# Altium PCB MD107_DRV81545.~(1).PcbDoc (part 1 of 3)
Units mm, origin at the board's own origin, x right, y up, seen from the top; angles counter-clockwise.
Board outline 152.45 x 74.46 mm, 4 copper layers (Top Layer, Mid-Layer 1, Mid-Layer 2, Bottom Layer), stack 2.355 mm thick; 219 components, 121 nets, 695 pads, 224 vias.
Unrouted connection lines stored in the file: 85.
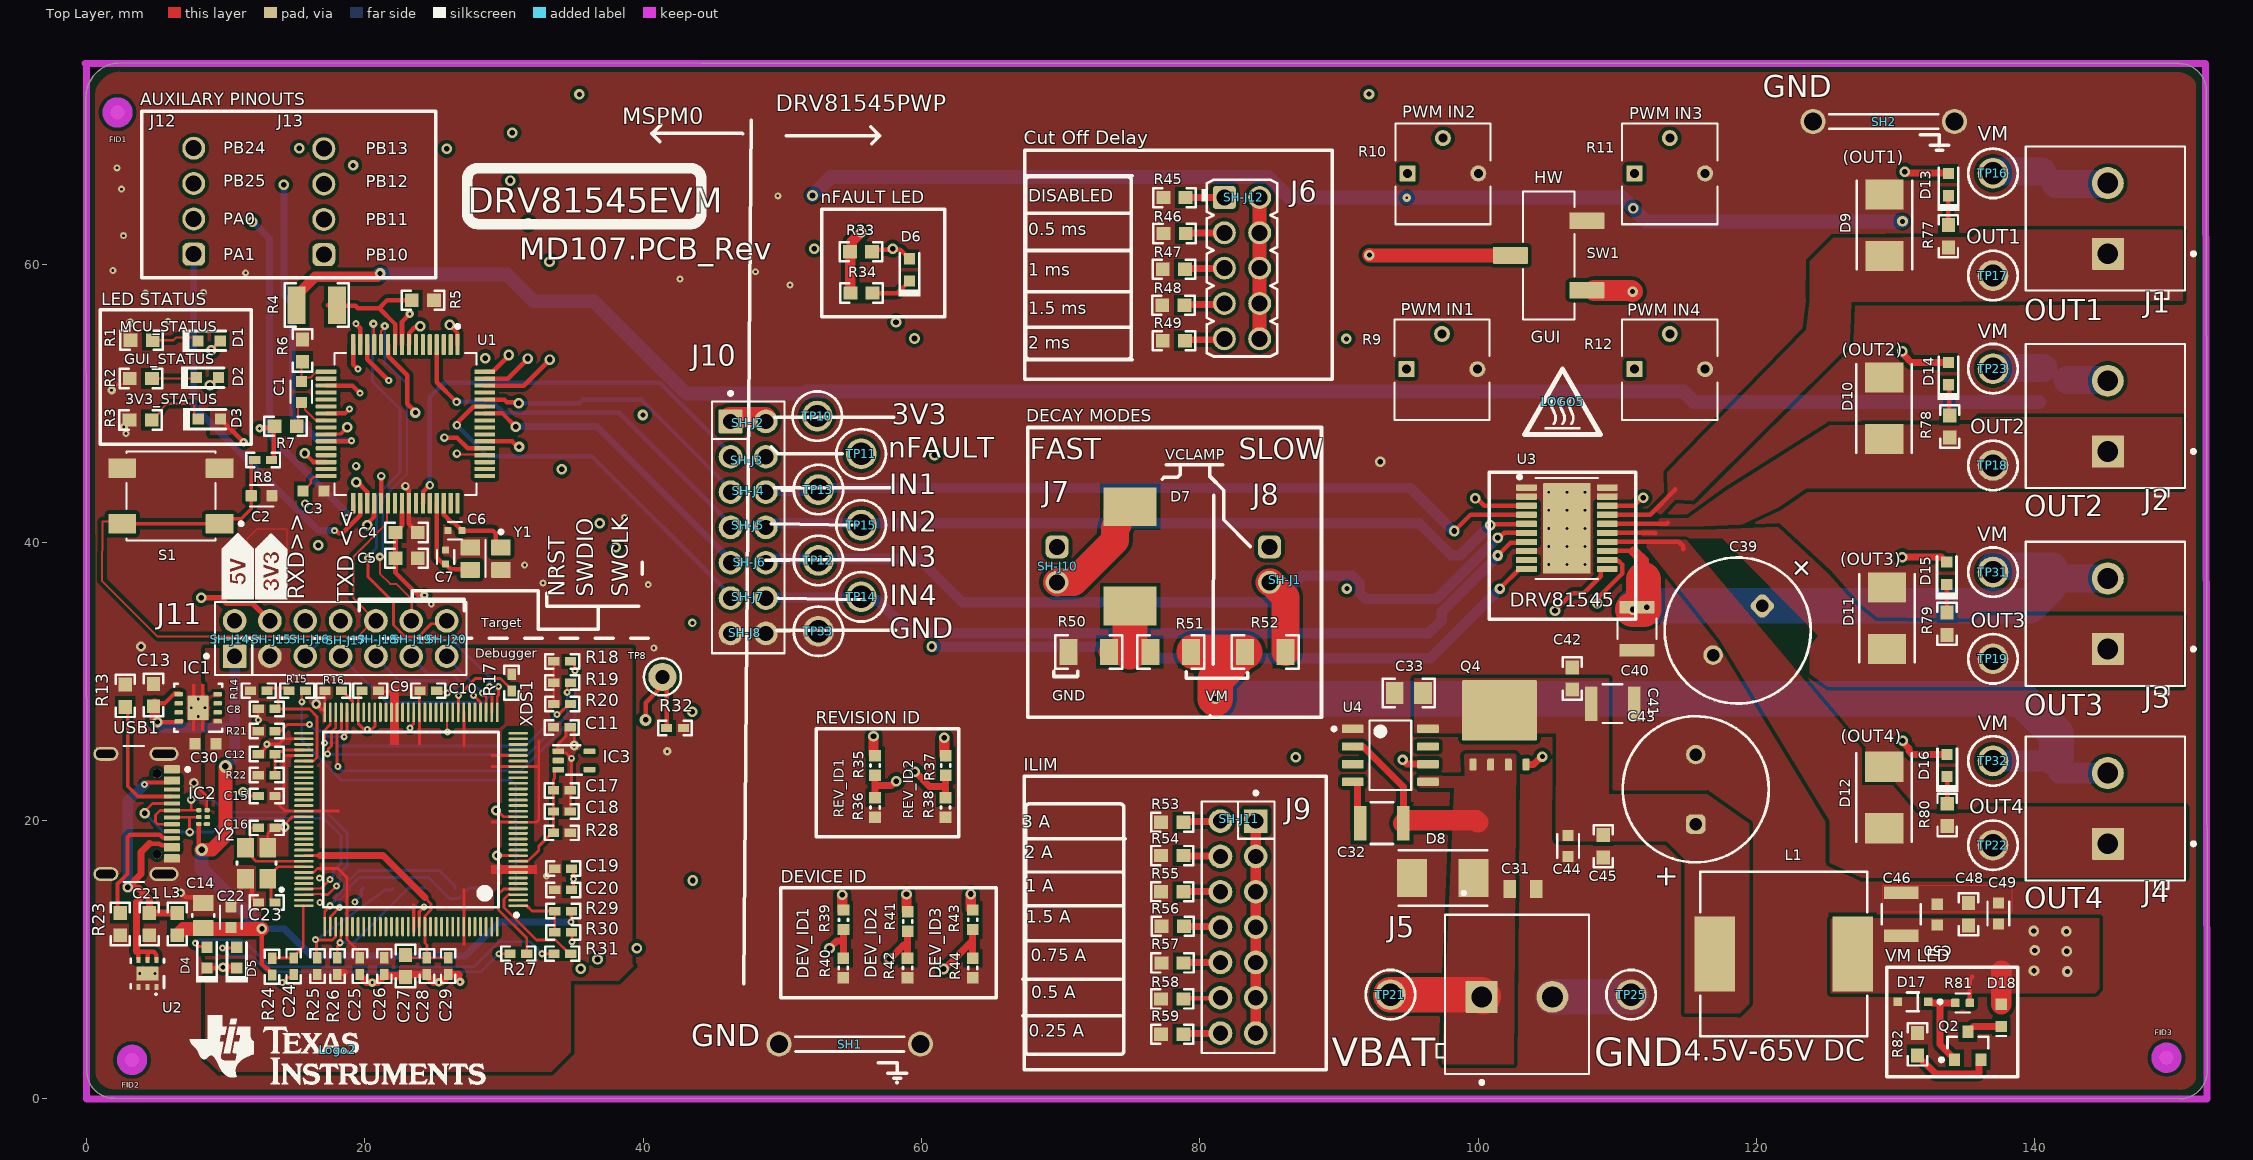
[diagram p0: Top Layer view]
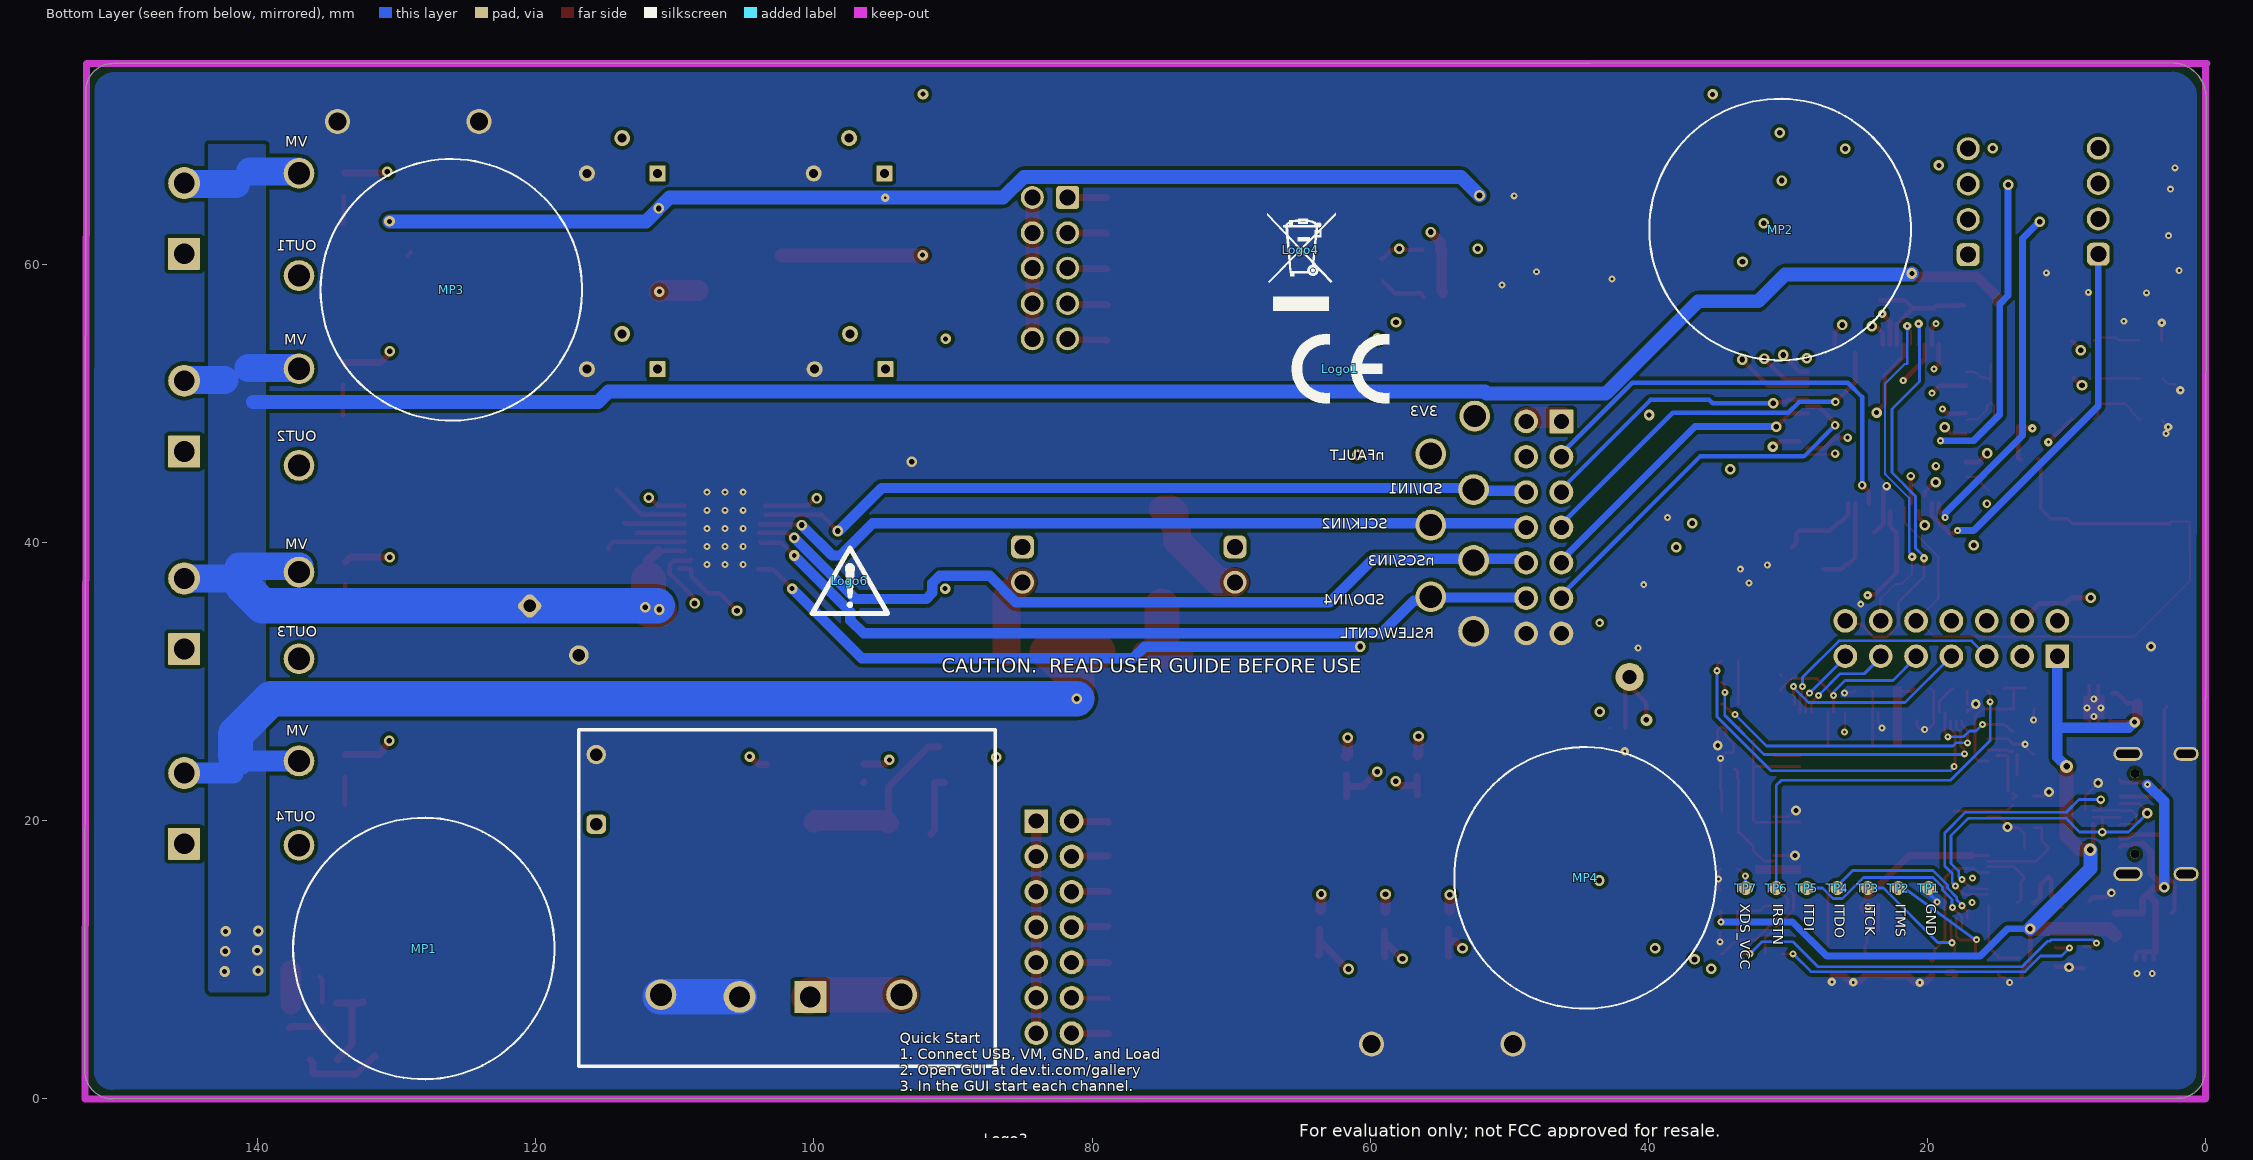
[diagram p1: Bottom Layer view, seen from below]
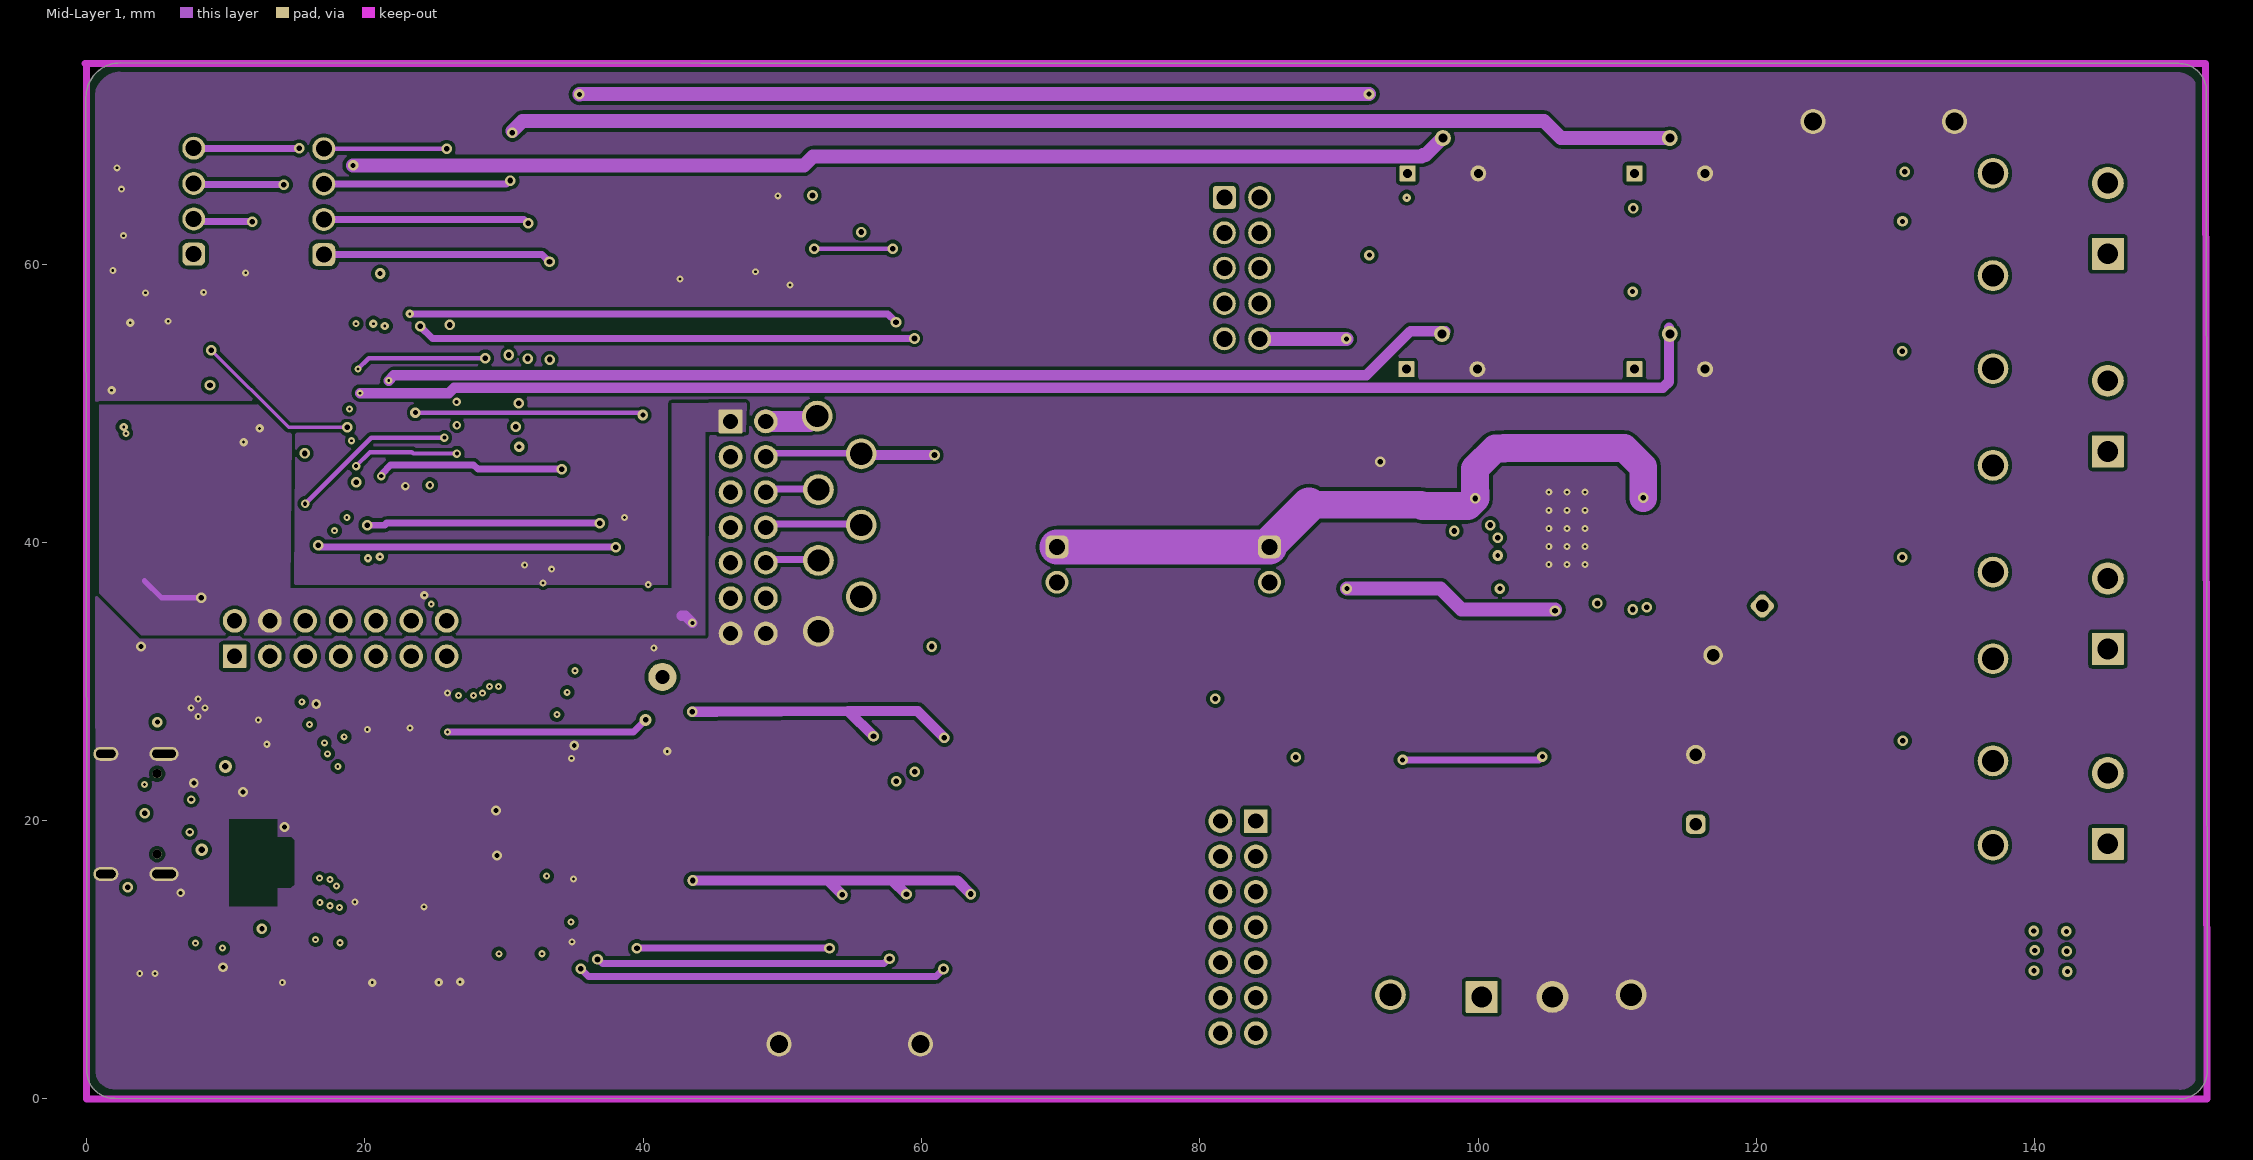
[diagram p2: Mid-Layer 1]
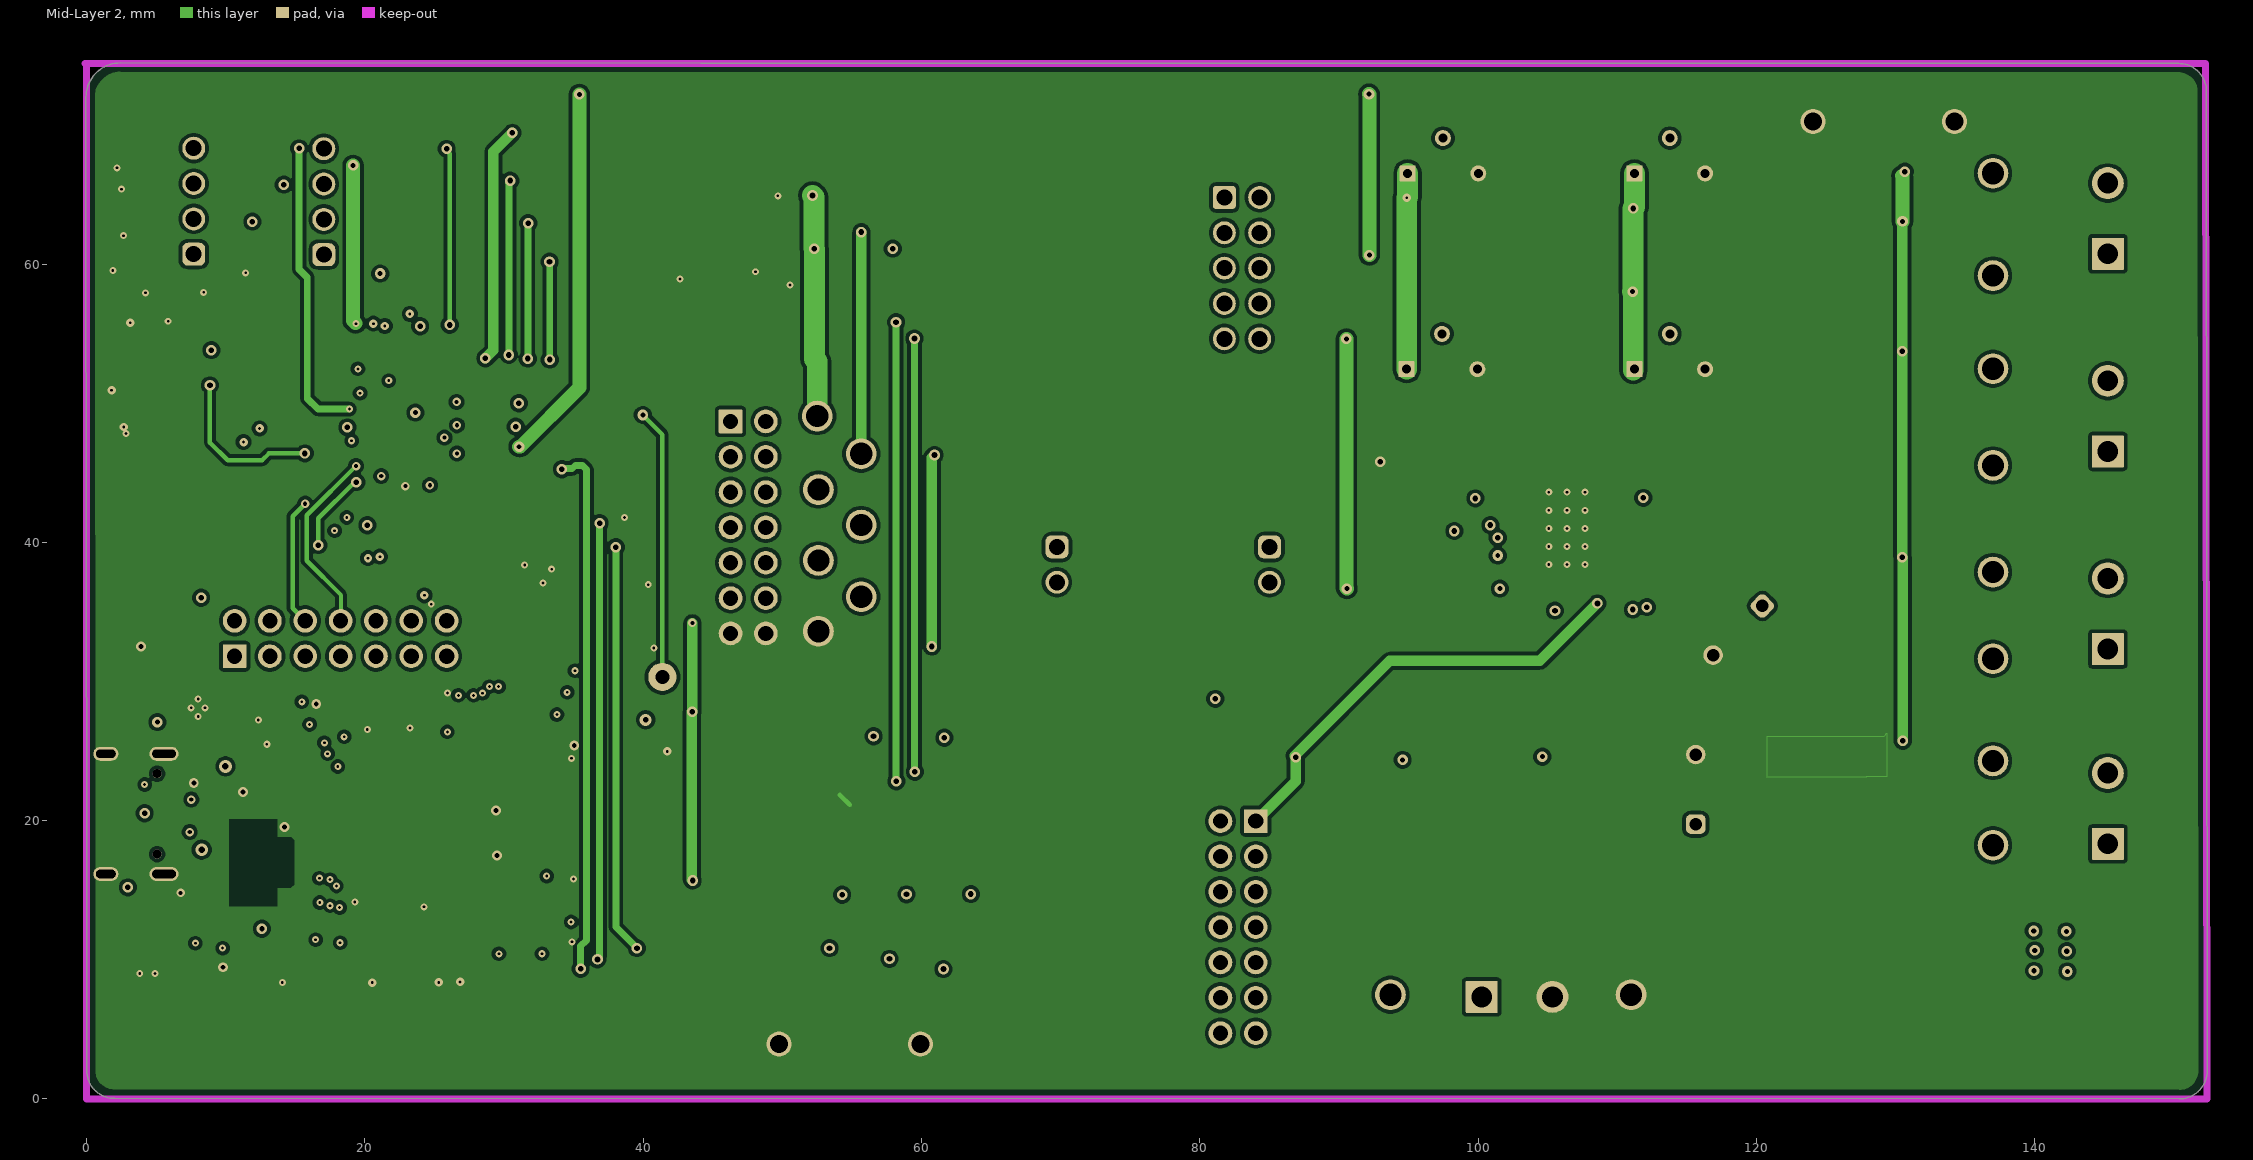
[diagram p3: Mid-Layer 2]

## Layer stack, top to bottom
Top Solder: solder mask 0.0102, Solder Resist, Dk 3.5
Top Layer: signal copper 0.07
Dielectric1: core 1.5037, FR-4 High Tg, Dk 4.8
Mid-Layer 1: signal copper 0.0356
Dielectric2: dielectric 0.32, FR-4, Dk 4.8
Mid-Layer 2: signal copper 0.0356
Dielectric3: dielectric 0.32, FR-4, Dk 4.8
Bottom Layer: signal copper 0.07
Bottom Solder: solder mask 0.0102, Solder Resist, Dk 3.5

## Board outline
0,15.58 0,17.163 -0.051,63.922 -0.051,71.99 cw(c2.42,71.99) 2.42,74.461 44.144,74.422 150.349,74.422 cw(c150.349,72.422) 152.349,72.422 152.4,2 cw(c150.4,2) 150.4,0 2,0.032 cw(c2,2.032) 0,2.032

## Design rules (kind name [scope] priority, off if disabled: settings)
AcuteAngle [All] p1: minimum=4.50000000000000E+0001 checktracksonly=FALSE
AssemblyTestPointUsage [All] p1: valid=2
BoardOutlineClearance BoardOutlineClearance_MountingHoles [OnCopper and InComponentClass('Mounting Holes')] p1: gap=0.381 ignorepadtopadclearanceinfootprint=FALSE
BoardOutlineClearance BoardOutlineClearance_Poly [OnCopper and IsPoly] p2: gap=0.635 ignorepadtopadclearanceinfootprint=FALSE
BoardOutlineClearance [OnCopper and Not InComponentClass('Logo') and not InComponentClass('FiducialMark') and not InRegion(1000,500,4000,800) and not InPoly] p3: gap=0.381 ignorepadtopadclearanceinfootprint=FALSE
Clearance Clearance_Keepouts [((IsTrack Or IsArc) And Not InPoly) And IsFree and IsKeepOut vs ((IsTrack Or IsArc) And Not InPoly) And IsFree and IsKeepOut] p1: gap=0 ignorepadtopadclearanceinfootprint=FALSE
Clearance Clearance_Poly [InPolygon] p2: gap=0.254 ignorepadtopadclearanceinfootprint=TRUE
Clearance Clearance_FiducialMark [IsKeepOut and InComponentClass('FiducialMark') vs IsPad and InComponentClass('FiducialMark')] p3: gap=0 ignorepadtopadclearanceinfootprint=TRUE
Clearance [All] p4: gap=0.152 ignorepadtopadclearanceinfootprint=TRUE
ComponentClearance ComponentClearance_Shunt [InComponentClass('Header') vs InComponentClass('Shunt')] p1: gap=0 collisioncheckmode=3 verticalgap=0 showdistances=FALSE
ComponentClearance ComponentClearance_PI_FILTER_R75 [InComponent('R75') vs InComponent('L1')] p2: gap=0 collisioncheckmode=3 verticalgap=0 showdistances=FALSE
ComponentClearance ComponentClearance_PI_FILTER_R66 [InComponent('R66') vs InComponent('L1')] p3: gap=0 collisioncheckmode=3 verticalgap=0 showdistances=FALSE
ComponentClearance ComponentClearance_CANL_Choke [InComponent('L2') vs InComponent('R71')] p4: gap=0 collisioncheckmode=3 verticalgap=0 showdistances=FALSE
ComponentClearance ComponentClearance_CANH_Choke [InComponent('L2') vs InComponent('R68')] p5: gap=0 collisioncheckmode=3 verticalgap=0 showdistances=FALSE
ComponentClearance ComponentClearance_MountingHoles_FiducialMarks [InComponentClass('Mounting Holes') vs InComponentClass('FiducialMark')] p6: gap=1.27 collisioncheckmode=3 verticalgap=0.254 showdistances=FALSE
ComponentClearance ComponentClearance_Logo [InComponentClass('Logo')] p7: gap=0.762 collisioncheckmode=3 verticalgap=0.254 showdistances=FALSE
ComponentClearance ComponentClearance_ScrewToNut [(HasFootprint('NY PMS 440 0025 PH')) vs (HasFootprint('Keystone_1902C'))] p8: gap=0.127 collisioncheckmode=3 verticalgap=0.254 showdistances=FALSE
ComponentClearance ComponentClearance_MountingHoles [InComponentClass('Mounting Holes')] p9: gap=2.54 collisioncheckmode=3 verticalgap=2540 showdistances=FALSE
ComponentClearance ComponentClearance_SmallPassives [HasFootprint('0201*') or HasFootprint('0402*') or HasFootprint('0508') or HasFootprint('0603*') or HasFootprint('0612') or HasFootprint('0805*') or HasFootprint('0815*') or HasFootprint('0830*') or HasFootprint('1206*') or HasFootprint('1210*') or HasFootprint('1808*') or HasFootprint('1812*') or HasFootprint('1825*') or HasFootprint('2010*') or HasFootprint('2220*') or HasFootprint('2225*') or HasFootprint('2512*') or HasFootprint('2728*') or HasFootprint('3518*') vs HasFootprint('0201*') or HasFootprint('0402*') or HasFootprint('0508') or HasFootprint('0603*') or HasFootprint('0612') or HasFootprint('0805*') or HasFootprint('0815*') or HasFootprint('0830*') or HasFootprint('1206*') or HasFootprint('1210*') or HasFootprint('1808*') or HasFootprint('1812*') or HasFootprint('1825*') or HasFootprint('2010*') or HasFootprint('2220*') or HasFootprint('2225*') or HasFootprint('2512*') or HasFootprint('2728*') or HasFootprint('3518*')] p10: gap=0.38 collisioncheckmode=3 verticalgap=0.254 showdistances=FALSE
ComponentClearance ComponentClearance_THtoSMT [IsThruComponent vs IsSMTComponent] p11: gap=0.762 collisioncheckmode=3 verticalgap=0.762 showdistances=FALSE
ComponentClearance ComponentClearance_THtoTH [IsThruComponent vs IsThruComponent] p12: gap=0.508 collisioncheckmode=3 verticalgap=0.762 showdistances=FALSE
ComponentClearance [All] p13: gap=0.508 collisioncheckmode=3 verticalgap=0.254 showdistances=FALSE
DiffPairsRouting [All] p1: maxlimit=2.54 minlimit=0.254 mostfreqgap=0.254 toplayer_minwidth=0.152 toplayer_maxwidth=0.381 toplayer_prefwidth=0.254 midlayer1_minwidth=0.152 midlayer1_maxwidth=0.381 midlayer1_prefwidth=0.254 midlayer2_minwidth=0.152 midlayer2_maxwidth=0.381 midlayer2_prefwidth=0.254 bottomlayer_minwidth=0.152 bottomlayer_maxwidth=0.381 bottomlayer_prefwidth=0.254 maxuncoupledlength=25.4
FabricationTestPointUsage TestPointUsage [All] p1: valid=2 allowmultiple=FALSE
FabricationTestpoint Testpoint [All] p1: side=3 testpointundercomponent=TRUE minsize=1.016 maxsize=2.54 preferedsize=1.524 minholesize=0 maxholesize=1.016 preferedholesize=0.813 testpointgrid=0.025 allowsidetop=TRUE allowsidebottom=TRUE usegrid=TRUE gridtolerance=0
FanoutControl Fanout_LCC [IsLCC] p1: bgadir=Out bgaviamode=Centered fanoutstyle=Auto fanoutdirection=Alternating viagrid=0.025 // Fanout_LCC (Default Rule)
FanoutControl Fanout_BGA [IsBGA] p2: bgadir=Out bgaviamode=Centered fanoutstyle=Auto fanoutdirection=Alternating viagrid=0.025 // Fanout_BGA (Default Rule)
FanoutControl Fanout_Default [All] p4: bgadir=Out bgaviamode=Centered fanoutstyle=Auto fanoutdirection=Alternating viagrid=0.025 // Fanout_Default (Default Rule)
FanoutControl Fanout_Small [(CompPinCount < 5)] p5: bgadir=Out bgaviamode=Centered fanoutstyle=Auto fanoutdirection=OutThenIn viagrid=0.025 // Fanout_Small (Default Rule)
HoleSize [All] p1: absolutevalues=TRUE maxlimit=6.375 minlimit=0.2 maxpercent=80.000 minpercent=20.000
MinimumAnnularRing MinimumAnnularRing_ThermalPadVias [IsVia and InAnyComponent] p1: minimumring=0.15
MinimumAnnularRing [All] p2: minimumring=0.15
MinimumSolderMaskSliver MinimumSolderMaskSliver_Logo [InComponentClass('Logo') vs InComponentClass('Logo')] p1: minsoldermaskwidth=0.018
MinimumSolderMaskSliver [All] p2: minsoldermaskwidth=0.1
PlaneClearance [All] p1: clearance=0.254
PlaneConnect [All] p1: planeconnectstyle=Direct reliefexpansion=0.254 reliefentries=4 reliefconductorwidth=0.254 reliefairgap=0.254
PolygonConnect [All] p1: connectstyle=Direct reliefconductorwidth=0.254 reliefentries=4 polygonreliefangle="90 Angle" airgapwidth=0.254
RoutingVias ThermalPadVias [IsVia and InAnyComponent] p1: holewidth=0.2 width=0.5 viastyle="Through Hole" minholewidth=0.2 minwidth=0.5 maxholewidth=0.33 maxwidth=0.6
RoutingVias [All] p2: holewidth=0.406 width=0.864 viastyle="Through Hole" minholewidth=0.2 minwidth=0.5 maxholewidth=6 maxwidth=6
SilkToBoardRegionClearance [Not ((IsComment or IsDesignator) And (Hide <> 'False')) and not InRegion(1000,500,4000,800)] p1:
SilkToSilkClearance SilkToSilkClearance_Pb-FreeLogo [(HasFootprint('Pb-Free_Overlay_Medium') OR HasFootprint('Pb-Free_Overlay_Small')) vs (HasFootprint('Pb-Free_Overlay_Medium') OR HasFootprint('Pb-Free_Overlay_Small'))] p1: silktosilkclearance=0
SilkToSilkClearance [All] p2: silktosilkclearance=0.1
SilkToSolderMaskClearance SilkToComponentPadClearance [(IsPad or IsFill or IsRegion) and InAnycomponent] p1: minsilkscreentomaskgap=0.127 clearancetoexposedcopper=TRUE
SilkToSolderMaskClearance "Silk to Solder Mask Opening" [All] p2: minsilkscreentomaskgap=0.1 clearancetoexposedcopper=FALSE
SolderMaskExpansion [All] p1: expansion=0.05 istentingtop=FALSE
UnRoutedNet [All] p1: checkbadconnections=TRUE
Width [All] p1: maxlimit=2.54 minlimit=0.152 preferedwidth=0.254 checkconnectedcopper=TRUE
13 further rules are at their usual default settings.

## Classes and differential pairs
component class MD107_DRV81545_Hardware: !PCB1 FID1 FID2 FID3 Logo1 Logo2 Logo3 Logo4 LOGO5 Logo6 MP1 MP2 MP3 MP4 ZZ1 ZZ2 ZZ3 ZZ4
component class MD107_DRV81545: 15 C31 C32 C33 C39 C40 C41 C42 C43 C44 C45 C46 C48 C49 C50 D7 D8 D9 D10 D11 D12 D13 D14 D15 D16 J1 J2 J3 J4 J5 J6 J7 J8 J9 L1 L? Q4 R45 R46 R47 R48 R49 R50 R51 R52 R53 R54 R55 R56 R57 R58 R59 R77 R78 R79 R80 SH1 SH2 SH-J1 SH-J10 SH-J11 SH-J12 TP16 TP17 TP18 TP19 TP21 TP22 TP23 TP25 TP31 TP32 U3 U4
component class MD107_DRV81545_XDS110: C8 C9 C10 C11 C12 C13 C14 C15 C16 C17 C18 C19 C20 C21 C22 C23 C24 C25 C26 C27 C28 C29 C30 D4 D5 IC1 IC2 IC3 J11 L3 R13 R14 R15 R16 R17 R18 R19 R20 R21 R22 R23 R24 R25 R26 R27 R28 R29 R30 R31 SH-J14 SH-J15 SH-J16 SH-J17 SH-J18 SH-J19 SH-J20 TP1 TP2 TP3 TP4 TP5 TP6 TP7 U2 USB1 XDS1 Y2
component class MD107_DRV81545_M0: 20 C1 C2 C3 C4 C5 C6 C7 D1 D2 D3 D6 D17 D18 J10 J12 J13 Q2 R1 R2 R3 R4 R5 R6 R7 R8 R9 R10 R11 R12 R32 R33 R34 R35 R36 R37 R38 R39 R40 R41 R42 R43 R44 R81 R82 S1 SH-J2 SH-J3 SH-J4 SH-J5 SH-J6 SH-J7 SH-J8 SW1 TP8 TP10 TP11 TP12 TP13 TP14 TP15 TP33 U1 Y1
differential pair XDS_USB_D: +XDS_USB_D_P -XDS_USB_D_N

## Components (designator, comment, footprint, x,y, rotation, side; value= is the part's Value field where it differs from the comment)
C1 "885012206126" FP-885012206126_0603-MFG 15.428,50.814 r270 top value=1µF
C2 "885012206065" FP-885012206065_0603-MFG 12.574,43.351 r0 top value=10nF
C3 "885012206075R" WCAP-CSGP_0603_L1.6W0.8H0.8_Reflow 16.308,43.688 r180 top value=470nF
C4 "885012206095" 0603 22.995,40.714 r0 top value=0.1uF
C5 "GRM188R61E106KA73D" 0603 22.995,38.862 r0 top value=10uF
C6 "885012005057" FP-885012005057_0402-MFG 26.477,40.841 r0 top value=22pF
C7 "885012005057" FP-885012005057_0402-MFG 25.793,38.948 r270 top value=22pF
C8 "GRM155R70J104KA01D" 0402 12.929,28.03 r180 top value=0.1uF
C9 "GRM155R71E103KA01D" 0402 20.38,29.336 r180 top value=0.01uF
C10 "GRM155R71E103KA01D" 0402 24.557,29.336 r0 top value=0.01uF
C11 "GRM155R71E103KA01D" 0402 34.156,26.709 r0 top value=0.01uF
C12 "GRM155R70J104KA01D" 0402 12.929,24.78 r180 top value=0.1uF
C13 "885012206052" 0603 4.801,29.02 r90 top value=1uF
C14 "885012107014" 0805_150 8.38,13.193 r90 top value=10uF
C15 "GRM155R71E103KA01D" 0402 12.929,21.772 r180 top value=0.01uF
C16 "GRM1555C1H120JA01D" 0402 12.929,19.488 r0 top value=12pF
C17 "GRM155R70J104KA01D" 0402 34.156,22.174 r0 top value=0.1uF
C18 "GRM155R71E103KA01D" 0402 34.156,20.651 r0 top value=0.01uF
C19 "C1005X5R1E105K050BC" 0402 34.244,16.545 r0 top value=1uF
C20 "GRM155R70J104KA01D" 0402 34.244,15.022 r0 top value=0.1uF
C21 "885012206089" 0603 4.502,12.562 r270 top value=0.01uF
C22 "885012206095" FP-885012206095_0603-MFG 10.369,13.065 r90 top value=100nF
C23 "GRM1555C1H120JA01D" 0402 12.939,14.113 r180 top value=12pF
C24 "GRM155R70J104KA01D" 0402 14.88,9.535 r270 top value=0.1uF
C25 "GRM155R70J104KA01D" 0402 19.637,9.549 r270 top value=0.1uF
C26 "C1005X5R1E105K050BC" 0402 21.387,9.549 r270 top value=1uF
C27 "C0603C225K8PACTU" 0603 22.919,9.549 r270 top value=2.2uF
C28 "GRM155R70J104KA01D" 0402 24.452,9.549 r270 top value=0.1uF
C29 "C1005X5R1E105K050BC" 0402 25.985,9.549 r270 top value=1uF
C30 "885012206027" WCAP-CSGP_0603_L1.6W0.8H0.8_Reflow 8.536,25.522 r0 top value=2.2µF
C31 "885012207124" WCAP-CSGP_0805_L2W1.25H0.8_Reflow 103.219,15.083 r180 top
C32 "885382209002" WCAP-CSST_1210_L3.2W2.5H2.5 93.088,19.816 r0 top
C33 "C2012X7S2A105K125AB" 0805_HV 95.025,29.173 r180 top value=1uF
C39 "860040875002" WCAP-ATUL_D10H12.5 118.663,33.661 r45 top value=47uF
C40 "885012209069" FP-885012209069_1210-MFG 111.418,33.791 r90 top value=1µF
C41 "885012209069" FP-885012209069_1210-MFG 109.671,28.403 r180 top value=1µF
C42 "885012206114" 0603 106.777,30.211 r270 top value=0.01uF
C43 "860040875004" WCAP-ATUL_D10H20 115.648,22.25 r270 top
C44 "885012206120" FP-885012206120_0603-MFG 106.467,18.171 r90 top value=100nF
C45 "06031C102KAT2A" 0603 109.006,18.157 r270 top value=1000pF
C46 "885012209069" FP-885012209069_1210-MFG 130.419,13.271 r270 top value=1µF
C48 "885012206114" 0603 135.251,13.271 r270 top value=0.01uF
C49 "885012206120" FP-885012206120_0603-MFG 137.404,13.319 r270 top value=100nF
C50 "885012206108" WCAP-CSGP_0603_L1.6W0.8H0.8_Reflow 133.003,13.243 r270 top value=1nF
D1 "150060VS75000" WL-SMCW_GREEN 8.796,54.484 r0 top value=Green
D2 "150060VS75000" WL-SMCW_GREEN 8.672,51.839 r0 top value=Green
D3 "150060VS75000" WL-SMCW_GREEN 8.814,48.858 r0 top value=Green
D4 "LTST-C190KRKT" LED_LTST-C190_Red 8.652,10.149 r270 top value=Red
D5 "LTST-C190GKT" LED_LTST-C190 10.785,10.149 r270 top value=Green
D6 "150060RS75000" WL-SMCW_RED 59.133,59.582 r90 top value=Red
D7 "SMCJ33CA" SMC_Bi 75.003,38.989 r270 top value=33V
D8 "SMBJ33CA-13-F" SMB-Bi 97.479,15.883 r0 top value=33V
D9 "SMBJ33CA-13-F" SMB-Bi 129.211,62.802 r270 top value=33V
D10 "SMBJ33CA-13-F" SMB-Bi 129.194,49.633 r270 top value=33V
D11 "SMBJ33CA-13-F" SMB-Bi 129.385,34.54 r270 top value=33V
D12 "SMBJ33CA-13-F" SMB-Bi 129.194,21.662 r270 top value=33V
D13 "150060VS75000" WL-SMCW_GREEN 133.815,65.716 r90 top value=Green
D14 "150060VS75000" WL-SMCW_GREEN 133.819,52.13 r90 top value=Green
D15 "150060VS75000" WL-SMCW_GREEN 133.692,37.78 r90 top value=Green
D16 "150060VS75000" WL-SMCW_GREEN 133.716,23.965 r90 top value=Green
D17 "BZX84J-B4V7,115" FP-SOD323F-MFG 131.257,6.979 r180 top
D18 "150060SS75000" WL-SMCW_0603_150060xx75000 137.603,6.004 r90 top
FID1 "Fiducial" Fiducial10-20 2.219,70.898 r0 top
FID2 "Fiducial" Fiducial10-20 3.256,2.806 r0 top
FID3 "Fiducial" Fiducial10-20 149.477,2.961 r0 top
IC1 "TPS73533DRBT" DRB0008A 8.011,28.107 r180 top
IC2 "TPD4E004DRYR" DRY0006A 8.361,20.25 r180 top
IC3 "LM4040C25IDCKR" DCK0005A_N 35.017,24.322 r0 top
J1 "691236510002" FP-691236510002_HHR2-MFG 145.088,62.982 r90 top
J2 "691236510002" FP-691236510002_HHR2-MFG 145.088,48.774 r90 top
J3 "691236510002" FP-691236510002_HHR2-MFG 145.088,34.566 r90 top
J4 "691236510002" FP-691236510002_HHR2-MFG 145.088,20.576 r90 top
J5 "691236510002" FP-691236510002_HHR2-MFG 102.507,7.508 r0 top
J6 "61301021121" WURTH_61301021121 83.036,59.71 r270 top
J7 "61300211121" WURTH_61300211121 69.737,38.403 r270 top
J8 "61300211121" WURTH_61300211121 85.011,38.401 r270 top
J9 "61301421121" FP-61301421121_HDR14-MFG#1 82.756,12.348 r270 top
J10 "61301421121" FP-61301421121_HDR14-MFG#2 47.545,41.072 r270 top
J11 "61301421121" FP-61301421121_HDR14-MFG#2 18.248,33.089 r0 top locked
J12 "61300411121" WURTH_61300411121 7.693,64.52 r90 top
J13 "61300411121" WURTH_61300411121 17.041,64.485 r90 top
L1 "7443320100" WE-HCC_1210 121.972,10.417 r0 top value=1uH
L3 "742863160" 0603 6.504,12.562 r270 top value="600 ohm"
Logo1 "CE Mark" CE_Mark_5mm 62.166,52.477 r180 bottom
Logo2 "Texas Instruments" TI_Stacked_Overlay_Small 18.037,3.526 r0 top
Logo3 "FCC disclaimer" FCC_disclaimer -17.907,49.43 r90 bottom
Logo4 "WEEE logo" WEEE_Minimum 65.004,61.033 r180 bottom
LOGO5 "CAUTION HOT SURFACE" IEC_HotSurface_Small 106.071,50.12 r0 top
Logo6 "CAUTION.  READ USER GUIDE BEFORE USE" IEC_Caution_Small 97.413,37.243 r180 bottom
MP1 "RBS-37BK" FP-RBS-37BK_BUMPER_CYLI-MFG 128.042,10.809 r180 bottom
MP2 "RBS-37BK" FP-RBS-37BK_BUMPER_CYLI-MFG 30.558,62.484 r180 bottom
MP3 "RBS-37BK" FP-RBS-37BK_BUMPER_CYLI-MFG 126.066,58.15 r180 bottom
MP4 "RBS-37BK" FP-RBS-37BK_BUMPER_CYLI-MFG 44.575,15.883 r180 bottom
Q2 "BC846BLT1G" ONSC-SOT-23-3-318-08_V 135.204,3.811 r90 top
Q4 "CSD19502Q5B" DNK0008A 101.543,26.848 r90 top value=80V
R1 "RC0603JR-07330RL" 0603 3.945,54.525 r0 top value=330
R2 "RC0603JR-07330RL" 0603 3.892,51.778 r0 top value=330
R3 "RC0603JR-07330RL" 0603 3.874,48.797 r0 top value=330
R4 "RC1210JR-0720KL" 1210 16.534,57.05 r180 top value=20k
R5 "RC0603JR-071KL" 0603 24.16,57.4 r180 top value=1.0k
R6 "Resistor" 0603 15.504,53.779 r270 top value=0
R7 "Resistor" 0603 14.296,48.339 r0 top value=0
R8 "CRCW040247K0JNED" 0402 12.674,45.924 r0 top value=47k
R9 "3362P-1-104TLF" FP-3362P-1-104TLF_PTH_TRIMMER_6MM60_6MM99-MFG 97.409,52.412 r0 top value=100kΩ
R10 "3362P-1-104TLF" FP-3362P-1-104TLF_PTH_TRIMMER_6MM60_6MM99-MFG 97.48,66.481 r0 top value=100kΩ
R11 "3362P-1-104TLF" FP-3362P-1-104TLF_PTH_TRIMMER_6MM60_6MM99-MFG 113.781,66.481 r0 top value=100kΩ
R12 "3362P-1-104TLF" FP-3362P-1-104TLF_PTH_TRIMMER_6MM60_6MM99-MFG 113.781,52.412 r0 top value=100kΩ
R13 "RC0603JR-075K1L" 0603 2.766,28.972 r90 top value=5.1k
R14 "CRCW040210K0JNED" 0402 12.367,29.336 r180 top value=10k
R15 "CRCW0402100RJNED" 0402 15.128,29.336 r180 top value=100
R16 "CRCW04024K87FKED" 0402 17.721,29.336 r0 top value=4.87k
R17 "ERJ-2RKF3301X" 0402 30.545,29.919 r90 top value=3.30k
R18 "CRCW04021K00JNED" 0402 34.168,31.452 r180 top value=1.0k
R19 "CRCW04021K00JNED" 0402 34.168,29.919 r180 top value=1.0k
R20 "CRCW04021K00JNED" 0402 34.168,28.386 r180 top value=1.0k
R21 "CRCW04021K00JNED" 0402 12.929,26.433 r180 top value=1.0k
R22 "CRCW040251R0JNED" 0402 12.929,23.27 r180 top value=51
R23 "RC0603JR-075K1L" 0603 2.406,12.562 r270 top value=5.1k
R24 "CRCW0402100RJNED" 0402 13.327,9.509 r90 top value=100
R25 "CRCW040210K0JNED" 0402 16.576,9.549 r90 top value=10k
R26 "CRCW040210K0JNED" 0402 18.011,9.549 r90 top value=10k
R27 "CRCW0402470RJNED" 0402 31.026,10.434 r0 top value=470
R28 "CRCW04021K00JNED" 0402 34.156,19.128 r0 top value=1.0k
R29 "RC0402FR-07330KL" 0402 34.244,13.499 r180 top value=330k
R30 "RC0402FR-07220KL" 0402 34.244,11.976 r180 top value=220k
R31 "CRCW0402470RJNED" 0402 34.19,10.434 r0 top value=470
R32 "CRCW040247K0JNED" 0402 42.282,26.66 r180 top value=47k
R33 "RC0603FR-074K99L" 0603 55.65,60.884 r0 top value=4.99k
R34 "RC0603JR-07330RL" 0603 55.684,57.915 r0 top value=330
R35 "RC0603JR-0710KL" 0603L 56.666,23.964 r270 top value=10k
R36 "RC0603JR-0710KL" 0603L 56.666,20.947 r270 top value=10k
R37 "RC0603JR-0710KL" 0603L 61.738,23.964 r270 top value=10k
R38 "RC0603JR-0710KL" 0603L 61.723,20.947 r270 top value=10k
R39 "RC0603JR-0710KL" 0603L 54.387,12.868 r270 top value=10k
R40 "RC0603JR-0710KL" 0603L 54.379,9.406 r270 top value=10k
R41 "RC0603JR-0710KL" 0603L 59.009,12.753 r270 top value=10k
R42 "RC0603JR-0710KL" 0603L 59.005,9.406 r270 top value=10k
R43 "RC0603JR-0710KL" 0603L 63.678,12.868 r270 top value=10k
R44 "RC0603JR-0710KL" 0603L 63.678,9.406 r270 top value=10k
R45 "RC0603FR-0710KL" 0603 78.183,64.778 r0 top value=10.0k
R46 "RC0603FR-0760K4L" 0603 78.191,62.205 r0 top value=60.4k
R47 "RC0603FR-07120KL" 0603 78.137,59.63 r0 top value=120k
R48 "RC0603FR-07180KL" 0603 78.102,57.05 r0 top value=180k
R49 "RC0603FR-07240KL" 0603 78.137,54.493 r0 top value=240k
R50 "CRCW12060000Z0EAHP" 1206 72.021,32.119 r0 top value=0
R51 "CRCW12060000Z0EAHP" 1206 77.907,32.119 r0 top value=0
R52 "CRCW12060000Z0EAHP" 1206 84.702,32.119 r180 top value=0
R53 "RC0603FR-0710KL" 0603 78.021,19.881 r0 top value=10.0k
R54 "RC0603FR-0730KL" 0603 78.021,17.487 r0 top value=30.0k
R55 "RC0603FR-0740K2L" 0603 78.021,14.894 r0 top value=40.2k
R56 "RC0603FR-0760K4L" 0603 78.058,12.41 r0 top value=60.4k
R57 "RC0603FR-0780K6L" 0603 78.035,9.777 r0 top value=80.6k
R58 "RC0603FR-07120KL" 0603 78.021,7.19 r0 top value=120k
R59 "RC0603FR-07240KL" 0603 78.021,4.65 r0 top value=240k
R77 "RC0603JR-07330RL" 0603 133.806,62.003 r90 top value=330
R78 "RC0603JR-07330RL" 0603 133.899,48.323 r90 top value=330
R79 "RC0603JR-07330RL" 0603 133.705,34.15 r90 top value=330
R80 "RC0603JR-07330RL" 0603 133.716,20.415 r90 top value=330
R81 "RCC040247K0FKED" FP-RCC040247K0FKED_0402-MFG 134.828,6.898 r0 top value=47k
R82 "RC0603FR-07470RL" 0603 131.59,3.924 r270 top value=470
S1 "430481025816" FP-430481025816_SMT_SW_6MM2_6MM2-MFG 6.053,43.342 r180 top
SH1 "Jumper_2p" Harwin_D3082-05 54.839,3.937 r180 top
SH2 "Jumper_2p" Harwin_D3082-05 129.159,70.247 r180 top
SH-J1 "60900213421" Wurth_60900213421 86.095,37.299 r180 top
SH-J2 "60900213421" Wurth_60900213421 47.498,48.585 r180 top
SH-J3 "60900213421" Wurth_60900213421 47.431,45.914 r180 top
SH-J4 "60900213421" Wurth_60900213421 47.564,43.71 r180 top
SH-J5 "60900213421" Wurth_60900213421 47.498,41.239 r180 top
SH-J6 "60900213421" Wurth_60900213421 47.631,38.568 r180 top
SH-J7 "60900213421" Wurth_60900213421 47.498,36.097 r180 top
SH-J8 "60900213421" Wurth_60900213421 47.297,33.493 r180 top
SH-J10 "60900213421" Wurth_60900213421 69.801,38.301 r270 top
SH-J11 "60900213421" Wurth_60900213421 82.822,20.138 r180 top
SH-J12 "60900213421" Wurth_60900213421 83.156,64.811 r0 top
SH-J14 "60900213421" Wurth_60900213421 10.303,33.026 r270 top
SH-J15 "60900213421" Wurth_60900213421 13.308,33.026 r270 top
SH-J16 "60900213421" Wurth_60900213421 16.046,33.026 r270 top
SH-J17 "60900213421" Wurth_60900213421 18.65,32.959 r270 top
SH-J18 "60900213421" Wurth_60900213421 20.921,33.026 r270 top
SH-J19 "60900213421" Wurth_60900213421 23.391,33.026 r270 top
SH-J20 "60900213421" Wurth_60900213421 25.862,33.026 r270 top
SW1 "450406020024" FP-450406020024_SMT_SW_9MM0_3MM5-MFG 105.075,60.623 r90 top
TP1 "TESTPOINT" TP_SM_1MM 19.878,15.153 r180 bottom
TP2 "TESTPOINT" TP_SM_1MM 22.071,15.153 r180 bottom
TP3 "TESTPOINT" TP_SM_1MM 24.264,15.153 r180 bottom
TP4 "TESTPOINT" TP_SM_1MM 26.457,15.153 r180 bottom
TP5 "TESTPOINT" TP_SM_1MM 28.65,15.153 r180 bottom
TP6 "TESTPOINT" TP_SM_1MM 30.843,15.153 r180 bottom
TP7 "TESTPOINT" TP_SM_1MM 33.036,15.153 r180 bottom
TP8 "5002" Keystone5002 41.377,30.328 r90 top
TP10 "5012" Keystone5012 52.505,49.076 r90 top
TP11 "5012" Keystone5012 55.663,46.36 r90 top
TP12 "5012" Keystone5012 52.592,38.699 r90 top
TP13 "5012" Keystone5012 52.592,43.794 r90 top
TP14 "5012" Keystone5012 55.663,36.083 r90 top
TP15 "5012" Keystone5012 55.663,41.245 r90 top
TP16 "5010" Keystone5010 137.012,66.521 r270 top
TP17 "5012" Keystone5012 137.012,59.176 r270 top
TP18 "5012" Keystone5012 137.012,45.528 r270 top
TP19 "5012" Keystone5012 137.012,31.63 r270 top
TP21 "5010" Keystone5010 93.707,7.491 r90 top
TP22 "5012" Keystone5012 137.012,18.234 r270 top
TP23 "5010" Keystone5010 137.012,52.487 r270 top
TP25 "5011" Keystone5011 111.001,7.491 r90 top
TP31 "5010" Keystone5010 137.012,37.864 r90 top
TP32 "5010" Keystone5010 137.012,24.289 r90 top
TP33 "5012" Keystone5012 52.592,33.61 r90 top
U1 "MSPM0G3507SPM" PM0064A-MFG 22.912,48.514 r270 top
U2 "TVS0500DRVR" DRV0006A 4.364,9.014 r90 top
U3 "DRV81545PWP" PWP0020AC-MFG 106.385,41.007 r0 top
U4 "LM74700D-Q1" D0008A-MFG 93.701,24.692 r0 top
USB1 "629722000214" FP-629722000214_CONN_USB-MFG 2.522,20.484 r270 top
XDS1 "MSP432E401YTPDTR" PDT0128A 23.307,20.08 r180 top
Y1 "X1E0000210179" FP-X1E0000210179_TSX-3225-MFG 28.674,38.828 r180 top
Y2 "NX3225GA-16.000M-STD-CRG-1" NDK_NX3225GA 12.21,16.939 r180 top
ZZ1 "This Assembly Note is for PCB labels only" AssemblyNoteLabel 1.982,197.104 r0 top
ZZ2 "These assemblies are ESD sensitive, ESD precautions shall be observed." AssemblyNote 2.108,194.107 r0 top
ZZ3 "These assemblies must be clean and free from flux and all contaminants. Use of no clean flux is not acceptable." AssemblyNote 2.083,190.932 r0 top
ZZ4 "These assemblies must comply with workmanship standards IPC-A-610 Class 2, unless otherwise specified." AssemblyNote 2.083,187.249 r0 top

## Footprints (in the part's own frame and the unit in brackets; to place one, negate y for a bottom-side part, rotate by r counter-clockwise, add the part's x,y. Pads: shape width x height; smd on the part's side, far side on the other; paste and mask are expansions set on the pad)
0402 [mm] "0402 from SM-752 data"
  rect 0.8x0.6 smd: 1(-0.6,0) 2(0.6,0)
  silkscreen extent -1.22,-0.52 1.22,0.52, body extent -0.55,-0.3 0.55,0.3, height 0.6
0603 [mm] "0603 from SM-752 data"
  rect 1x0.95 smd: 1(-0.8,0) 2(0.8,0)
  silkscreen extent -1.52,-0.69 1.52,0.69, body extent -0.87,-0.47 0.87,0.47, height 1
0603L [mm] "0603 from SM-752 data"
  rect 0.8x0.85 smd: 1(-0.7,0) 2(0.7,0)
  silkscreen extent -0.07,-0.32 0.07,0.32, body extent -0.87,-0.47 0.87,0.47, height 1
0805_150 [mm] "0805 / 1.5 mm height"
  rect 1.15x1.45 smd: 1(-0.9,0) 2(0.9,0)
  silkscreen extent -0.1,-0.8 0.1,0.8, body extent -1.1,-0.72 1.1,0.72, height 1.5
0805_HV [mil] "0805 with 30mil clearance between pads"
  rect 50x63 smd: 1(-40,0) 2(40,0)
  silkscreen extent -74,-40 74,40, body extent -43,-29 43,29, height 57
1206 [mm] "1206 from SM-752 data"
  rect 1.3x1.85 smd: 1(-1.45,0) 2(1.45,0)
  silkscreen extent -2.4,-1.21 2.4,1.21, body extent -1.7,-0.9 1.7,0.9, height 1.35
1210 [mm] "1210 from SM-752 data"
  rect 1.3x2.7 smd: 1(-1.45,0) 2(1.45,0)
  silkscreen extent -2.32,-1.57 2.32,1.57, body extent -1.7,-1.35 1.7,1.35, height 1.35
AssemblyNote [mm] "Assembly Note"
AssemblyNoteLabel [mm] "Assembly Note for PCB Labels"
CE_Mark_5mm [mm] "Minimum text height for CE Mark"
  silkscreen extent -3.5,-2.5 3.5,2.5
D0008A-MFG [mm] "Recommended Land Pattern"
  rrect17% 1.55x0.6 smd paste+0 mask+0: 1(-2.7,1.905) 2(-2.7,0.635) 3(-2.7,-0.635) 4(-2.7,-1.905) 5(2.7,-1.905) 6(2.7,-0.635) 7(2.7,0.635) 8(2.7,1.905)
  silkscreen extent -4.17,-2.5 1.5,2.5, body extent -3,-2.45 3,2.45, height 1.75
DCK0005A_N [mm] "SOT353, 5-Leads, Body 2x1.3mm, Pitch 0.65mm, Lead Span 2.1mm, IPC Medium Density"
  rrect25% 0.85x0.4 smd: 1(-1.125,0.65) 2(-1.125,0) 3(-1.125,-0.65) 4(1.125,-0.65) 5(1.125,0.65)
  silkscreen extent -1.48,-1.02 0.55,1.1, body extent -1.14,-1 1.14,1, height 0.95
DNK0008A [mm] "SON, 8-Leads, Body 5x6mm"
  rrect39% 0.86x0.51 smd paste-0.05 mask-0.05: 1(-2.82,1.905) 2(-2.82,0.635) 3(-2.82,-0.635) 4(-2.82,-1.905) 5(2.82,-1.905) 6(2.82,-0.635) 7(2.82,0.635) 8(2.82,1.905)
  rrect40% 0.25x0.555 on Top Solder: 9(-0.83,2.373) 9(-0.83,-2.373)
  rrect40% 0.25x0.555 on Top Paste: 9(-0.83,2.373) 9(-0.83,-2.373)
  rrect11% 0.95x1.13 on Top Paste: 9(-0.535,0) 9(-0.535,1.33) 9(-0.535,-1.33) 9(0.615,1.33) 9(0.615,-1.33) 9(0.615,0) 9(1.765,-1.33) 9(1.765,0) 9(1.765,1.33)
  rrect3% 3.58x4 on Top Solder: 9(0.75,0)
  rrect5% 4.34x5.4 smd paste-3 mask-3: 9(1.08,0)
  body extent -3.05,-2.55 3.05,2.55, height 1.06
DRB0008A [mm] "VSON-8"
  rrect32% 0.6x0.31 smd: 1(-1.4,0.975) 2(-1.4,0.325) 3(-1.4,-0.325) 4(-1.4,-0.975) 5(1.4,-0.975) 6(1.4,-0.325) 7(1.4,0.325) 8(1.4,0.975)
  rrect7% 1.5x1.75 smd paste-0.75: 9(0,0)
  Top Layer region: -0.7,-0.875 -0.49,-0.875 -0.471,-0.879 -0.455,-0.89 -0.444,-0.906 -0.44,-0.925 -0.44,-0.925 -0.44,-1.65 -0.436,-1.669 -0.425,-1.685 -0.409,-1.696 -0.39,-1.7 -0.39,-1.7 -0.26,-1.7 -0.241,-1.696 -0.225,-1.685 -0.214,-1.669 -0.21,-1.65 -0.21,-1.65 -0.21,-0.925 -0.206,-0.906 -0.195,-0.89 -0.179,-0.879 -0.16,-0.875 -0.16,-0.875 0.16,-0.875 0.179,-0.879 0.195,-0.89 0.206,-0.906 0.21,-0.925 0.21,-0.925 0.21,-1.65 0.21,-1.65 0.214,-1.669 0.225,-1.685 0.241,-1.696 0.26,-1.7 0.26,-1.7 0.39,-1.7 0.409,-1.696 0.425,-1.685 0.436,-1.669 0.44,-1.65 0.44,-1.65 0.44,-0.925 0.444,-0.906 0.455,-0.89 0.471,-0.879 0.49,-0.875 0.49,-0.875 0.7,-0.875 0.719,-0.871 0.735,-0.86 0.746,-0.844 0.75,-0.825 0.75,-0.825 0.75,0.825 0.746,0.844 0.735,0.86 0.719,0.871 0.7,0.875 0.7,0.875 0.49,0.875 0.471,0.879 0.455,0.89 0.444,0.906 0.44,0.925 0.44,0.925 0.44,1.65 0.436,1.669 0.425,1.685 0.409,1.696 0.39,1.7 0.39,1.7 0.26,1.7 0.241,1.696 0.225,1.685 0.214,1.669 0.21,1.65 0.21,1.65 0.21,1.65 0.21,0.925 0.206,0.906 0.195,0.89 0.179,0.879 0.16,0.875 0.16,0.875 -0.16,0.875 -0.179,0.879 -0.195,0.89 -0.206,0.906 -0.21,0.925 -0.21,0.925 -0.21,1.65 -0.214,1.669 -0.225,1.685 -0.241,1.696 -0.26,1.7 -0.26,1.7 -0.39,1.7 -0.409,1.696 -0.425,1.685 -0.436,1.669 -0.44,1.65 -0.44,1.65 -0.44,0.925 -0.444,0.906 -0.455,0.89 -0.471,0.879 -0.49,0.875 -0.49,0.875 -0.7,0.875 -0.719,0.871 -0.735,0.86 -0.746,0.844 -0.75,0.825 -0.75,0.825 -0.75,-0.825 -0.746,-0.844 -0.735,-0.86 -0.719,-0.871 -0.7,-0.875
  silkscreen extent -1.73,-1.73 1.73,1.73, body extent -1.5,-1.5 1.5,1.5, height 0.77
DRV0006A [mm] "SON, 6-Leads, Body 2x2mm, Pitch 0.65mm, Thermal Pad 1.6x1mm, TI Recommended"
  rrect33% 0.45x0.3 smd: 1(-0.975,-0.65) 2(-0.975,0) 3(-0.975,0.65) 4(0.975,0.65) 5(0.975,0) 6(0.975,-0.65)
  rrect14% 1x0.7 on Top Paste: 7(0,0.45) 7(0,-0.45)
  rrect10% 1x1.6 smd paste-0.5: 7(0,0)
  silkscreen extent -1.05,-1.2 1.05,1.2, body extent -1.05,-1.05 1.05,1.05, height 0.81
DRY0006A [mm] "USON-6"
  rrect67% 0.45x0.3 smd paste-0.05 mask-0.05: 1(-0.275,0.5)
  rrect67% 0.4x0.3 smd paste-0.05 mask-0.05: 2(-0.3,0) 3(-0.3,-0.5) 4(0.3,-0.5) 5(0.3,0) 6(0.3,0.5)
  body extent -0.5,-0.72 0.5,0.73, height 0.58
FCC_disclaimer [mm]
Fiducial10-20 [mm]
  round 1 smd mask+0.5: 1(0,0)
  Top Layer keep-out circle w1.178: c0,0 r0.5
FP-3362P-1-104TLF_PTH_TRIMMER_6MM60_6MM99-MFG [mm]
  rrect9% 1.15x1.15 hole 0.65 paste-1000 mask+0: 1(-2.54,0.035)
  round 1.15 hole 0.65 paste-1000 mask+0: 2(0,2.575) 3(2.54,0.035)
  silkscreen extent -3.42,-3.62 3.42,3.62, body extent -3.52,-3.72 3.52,3.72, height 0.25
FP-61301421121_HDR14-MFG#1 [mm]
  rrect6% 1.7x1.7 hole 1.1 paste-1000 mask+0: 1(-7.62,1.27)
  round 1.7 hole 1.1 paste-1000 mask+0: 2(-7.62,-1.27) 3(-5.08,1.27) 4(-5.08,-1.27) 5(-2.54,1.27) 6(-2.54,-1.27) 7(0,1.27) 8(0,-1.27) 9(2.54,1.27) 10(2.54,-1.27) 11(5.08,1.27) 12(5.08,-1.27) 13(7.62,1.27) 14(7.62,-1.27)
  silkscreen extent -9.76,-2.62 9.04,2.62, body extent -8.89,-2.54 8.89,2.54, height 8.89
FP-61301421121_HDR14-MFG#2 [mm]
  rrect6% 1.7x1.7 hole 1.1 paste-1000 mask+0: 1(-7.62,-1.27)
  round 1.7 hole 1.1 paste-1000 mask+0: 2(-7.62,1.27) 3(-5.08,-1.27) 4(-5.08,1.27) 5(-2.54,-1.27) 6(-2.54,1.27) 7(0,-1.27) 8(0,1.27) 9(2.54,-1.27) 10(2.54,1.27) 11(5.08,-1.27) 12(5.08,1.27) 13(7.62,-1.27) 14(7.62,1.27)
  silkscreen extent -9.76,-2.62 9.04,2.62, body extent -9.14,-2.72 9.14,2.72, height 0.25
FP-430481025816_SMT_SW_6MM2_6MM2-MFG [mm]
  rrect7% 2x1.4 smd paste+0 mask+0: 1(-3.5,2) 2(3.5,2) 3(-3.5,-2) 4(3.5,-2)
  silkscreen extent -5.18,-3.2 3.2,3.2, body extent -4.6,-3.3 4.6,3.3, height 0.25
FP-450406020024_SMT_SW_9MM0_3MM5-MFG [mm] "Recommended Land Pattern"
  rrect8% 1.2x2.5 smd paste+0 mask+0: 1(-2.5,-2.75) 2(0,2.75) 3(2.5,-2.75)
  silkscreen extent -4.6,-1.85 4.6,1.85, body extent -4.7,-4.1 4.7,4.1, height 0.25
FP-629722000214_CONN_USB-MFG [mm]
  rrect100% 1x2.1 hole 1.7 slot 0.6 at 0 deg paste-1000 mask+0: 1(-4.32,3.035) 2(4.32,3.035)
  rrect100% 1x1.8 hole 1.4 slot 0.6 at 0 deg paste-1000 mask+0: 3(-4.32,-1.145) 4(4.32,-1.145)
  rrect17% 0.6x1.15 smd paste+0 mask+0: A1-B12(-3.2,3.6) A4-B9(-2.4,3.6) A9-B4(2.4,3.6) A12-B1(3.2,3.6)
  rrect33% 0.3x1.15 smd paste+0 mask+0: A5(-1.25,3.6) A6(-0.25,3.6) A7(0.25,3.6) A8(1.25,3.6) B5(1.75,3.6) B6(0.75,3.6) B7(-0.75,3.6) B8(-1.75,3.6)
  round 0.65 hole 0.65 unplated paste-1000 mask+0: ""(-2.89,2.535) ""(2.89,2.535)
  silkscreen extent -4.89,0.13 4.89,4.86, body extent -4.99,-3.97 4.99,4.28, height 0.25
FP-691236510002_HHR2-MFG [mm]
  rrect4% 2.3x2.3 hole 1.5 paste-1000 mask+0: 1(-2.24,-0.175)
  round 2.3 hole 1.5 paste-1000 mask+0: 2(2.84,-0.175)
  silkscreen extent -5.48,-6.45 5.48,5.72, body extent -5.58,-5.82 5.58,5.82, height 0.25
FP-885012005057_0402-MFG [mm]
  rrect20% 0.5x0.5 smd paste+0 mask+0: 1(-0.5,0) 2(0.5,0)
  silkscreen extent -0.5,-0.63 0.5,0.63, body extent -0.85,-0.38 0.85,0.38, height 0.25
FP-885012206065_0603-MFG [mm]
  rrect13% 0.8x0.8 smd paste+0 mask+0: 1(-0.75,0) 2(0.75,0)
  silkscreen extent -0.85,-0.77 0.85,0.77, body extent -1.25,-0.55 1.25,0.55, height 0.25
FP-885012206095_0603-MFG [mm]
  rrect13% 0.8x0.8 smd paste+0 mask+0: 1(-0.75,0) 2(0.75,0)
  silkscreen extent -0.85,-0.77 0.85,0.77, body extent -1.25,-0.55 1.25,0.55, height 0.25
FP-885012206120_0603-MFG [mm]
  rrect13% 0.8x0.8 smd paste+0 mask+0: 1(-0.75,0) 2(0.75,0)
  silkscreen extent -0.85,-0.77 0.85,0.77, body extent -0.8,-0.4 0.8,0.4, height 0.87
FP-885012206126_0603-MFG [mm]
  rrect13% 0.8x0.8 smd paste+0 mask+0: 1(-0.75,0) 2(0.75,0)
  silkscreen extent -0.8,-0.77 0.8,0.77, body extent -1.25,-0.58 1.25,0.58, height 0.25
FP-885012209069_1210-MFG [mm]
  rrect11% 0.9x2.5 smd paste+0 mask+0: 1(-1.55,0) 2(1.55,0)
  silkscreen extent -0.72,-1.4 0.72,1.4, body extent -2.1,-1.5 2.1,1.5, height 0.25
FP-RBS-37BK_BUMPER_CYLI-MFG [mm]
  silkscreen extent -9.4,-9.4 9.4,9.4, body extent -9.14,-9.15 9.15,9.15, height 14.7
FP-RCC040247K0FKED_0402-MFG [mm]
  rrect17% 0.6x0.6 smd paste+0 mask+0: 1(-0.525,0) 2(0.525,0)
  silkscreen extent -0.53,-0.68 0.52,0.67, body extent -0.92,-0.4 0.92,0.4, height 0.25
FP-SOD323F-MFG [mm]
  rect 0.6x0.6 smd paste-1000 mask+0: 1(-1.1,0) 2(1.1,0)
  silkscreen extent -2.08,-0.67 0.43,0.67, body extent -1.53,-0.82 1.53,0.82, height 0.25
FP-X1E0000210179_TSX-3225-MFG [mm]
  rrect9% 1.4x1.15 smd paste+0 mask+0: 1(-1.1,-0.8) 2(1.1,-0.8) 3(1.1,0.8) 4(-1.1,0.8)
  silkscreen extent -1.22,-2.05 0,1.33, body extent -1.6,-1.25 1.6,1.25, height 0.6
Harwin_D3082-05 [mm] "Shorting Plug, 10.16mm spacing, TH"
  round 1.8 hole 1.3: 1(-5.08,0) 2(5.08,0)
  silkscreen extent -3.9,-0.53 3.9,0.53, body extent -5.6,-0.52 5.61,0.52, height 6.63
IEC_Caution_Small [mm]
  silkscreen extent -2.72,-2.36 2.72,2.35
IEC_HotSurface_Small [mm]
  silkscreen extent -2.72,-2.36 2.72,2.35
Keystone5002 [mil] "For Keystone 500x miniature loop terminals"
  round 80 hole 40: 1(0,0)
  silkscreen extent -52,-52 52,52, body extent -49,-49 49,49, height 182
Keystone5010 [mil] "Keystone Multipurpose loops"
  round 87 hole 63: 1(0,0)
  silkscreen extent -70,-70 70,70, body extent -63,-63 63,62, height 319
Keystone5011 [mil] "Keystone Multipurpose loops"
  round 87 hole 63: 1(0,0)
  silkscreen extent -70,-70 70,70, body extent -63,-63 63,62, height 319
Keystone5012 [mil] "Keystone Multipurpose loops"
  round 87 hole 63: 1(0,0)
  silkscreen extent -70,-70 70,70, body extent -63,-63 63,62, height 319
LED_LTST-C190 [mm] "Lite-On"
  rect 0.8x0.8 smd: 1(-0.75,0) 2(0.75,0)
  silkscreen extent -1.1,-0.8 1.8,0.8, body extent -0.85,-0.45 0.85,0.45, height 0.9
LED_LTST-C190_Red [mm] "Lite-On"
  rect 0.8x0.8 smd: 1(-0.75,0) 2(0.75,0)
  silkscreen extent -1.1,-0.8 1.8,0.8, body extent -0.85,-0.45 0.85,0.45, height 0.9
NDK_NX3225GA [mm] "NDK"
  rect 1.2x1.4 smd: 1(-0.8,1.1) 2(-0.8,-1.1) 3(0.8,-1.1) 4(0.8,1.1)
  silkscreen extent -1.9,-0.1 1.4,2, body extent -1.3,-1.65 1.3,1.65, height 0.9
ONSC-SOT-23-3-318-08_V [mm] "SOT23, 3-Leads, Body 2.92x1.3mm, Pitch 0.95mm"
  rect 0.9x0.8 smd: 1(-1,0.95) 2(-1,-0.95) 3(1,0)
  silkscreen extent -1.12,-1.46 0.65,2.02, body extent -0.65,-1.46 0.65,1.46, height 1.11
PDT0128A [mm] "Thin QFP, 128-Leads, Body 14x14mm, Pitch 0.4mm"
  oval 1.4x0.2 smd: 1(-7.7,6.2) 2(-7.7,5.8) 3(-7.7,5.4) 4(-7.7,5) 5(-7.7,4.6) 6(-7.7,4.2) 7(-7.7,3.8) 8(-7.7,3.4) 9(-7.7,3) 10(-7.7,2.6) 11(-7.7,2.2) 12(-7.7,1.8) 13(-7.7,1.4) 14(-7.7,1) 15(-7.7,0.6) 16(-7.7,0.2) 17(-7.7,-0.2) 18(-7.7,-0.6) 19(-7.7,-1) 20(-7.7,-1.4) 21(-7.7,-1.8) 22(-7.7,-2.2) 23(-7.7,-2.6) 24(-7.7,-3) 25(-7.7,-3.4) 26(-7.7,-3.8) 27(-7.7,-4.2) 28(-7.7,-4.6) 29(-7.7,-5) 30(-7.7,-5.4) 31(-7.7,-5.8) 32(-7.7,-6.2) 65(7.7,-6.2) 66(7.7,-5.8) 67(7.7,-5.4) 68(7.7,-5) 69(7.7,-4.6) 70(7.7,-4.2) 71(7.7,-3.8) 72(7.7,-3.4) 73(7.7,-3) 74(7.7,-2.6) 75(7.7,-2.2) 76(7.7,-1.8) 77(7.7,-1.4) 78(7.7,-1) 79(7.7,-0.6) 80(7.7,-0.2) 81(7.7,0.2) 82(7.7,0.6) 83(7.7,1) 84(7.7,1.4) 85(7.7,1.8) 86(7.7,2.2) 87(7.7,2.6) 88(7.7,3) 89(7.7,3.4) 90(7.7,3.8) 91(7.7,4.2) 92(7.7,4.6) 93(7.7,5) 94(7.7,5.4) 95(7.7,5.8) 96(7.7,6.2)
  oval 0.2x1.4 smd: 33(-6.2,-7.7) 34(-5.8,-7.7) 35(-5.4,-7.7) 36(-5,-7.7) 37(-4.6,-7.7) 38(-4.2,-7.7) 39(-3.8,-7.7) 40(-3.4,-7.7) 41(-3,-7.7) 42(-2.6,-7.7) 43(-2.2,-7.7) 44(-1.8,-7.7) 45(-1.4,-7.7) 46(-1,-7.7) 47(-0.6,-7.7) 48(-0.2,-7.7) 49(0.2,-7.7) 50(0.6,-7.7) 51(1,-7.7) 52(1.4,-7.7) 53(1.8,-7.7) 54(2.2,-7.7) 55(2.6,-7.7) 56(3,-7.7) 57(3.4,-7.7) 58(3.8,-7.7) 59(4.2,-7.7) 60(4.6,-7.7) 61(5,-7.7) 62(5.4,-7.7) 63(5.8,-7.7) 64(6.2,-7.7) 97(6.2,7.7) 98(5.8,7.7) 99(5.4,7.7) 100(5,7.7) 101(4.6,7.7) 102(4.2,7.7) 103(3.8,7.7) 104(3.4,7.7) 105(3,7.7) 106(2.6,7.7) 107(2.2,7.7) 108(1.8,7.7) 109(1.4,7.7) 110(1,7.7) 111(0.6,7.7) 112(0.2,7.7) 113(-0.2,7.7) 114(-0.6,7.7) 115(-1,7.7) 116(-1.4,7.7) 117(-1.8,7.7) 118(-2.2,7.7) 119(-2.6,7.7) 120(-3,7.7) 121(-3.4,7.7) 122(-3.8,7.7) 123(-4.2,7.7) 124(-4.6,7.7) 125(-5,7.7) 126(-5.4,7.7) 127(-5.8,7.7) 128(-6.2,7.7)
  silkscreen extent -7.7,-6.3 6.3,6.99, body extent -8,-8 8,8, height 1.07
PM0064A-MFG [mm]
  rrect33% 1.5x0.3 smd paste+0 mask+0: 1(-5.7,3.75) 2(-5.7,3.25) 3(-5.7,2.75) 4(-5.7,2.25) 5(-5.7,1.75) 6(-5.7,1.25) 7(-5.7,0.75) 8(-5.7,0.25) 9(-5.7,-0.25) 10(-5.7,-0.75) 11(-5.7,-1.25) 12(-5.7,-1.75) 13(-5.7,-2.25) 14(-5.7,-2.75) 15(-5.7,-3.25) 16(-5.7,-3.75) 33(5.7,-3.75) 34(5.7,-3.25) 35(5.7,-2.75) 36(5.7,-2.25) 37(5.7,-1.75) 38(5.7,-1.25) 39(5.7,-0.75) 40(5.7,-0.25) 41(5.7,0.25) 42(5.7,0.75) 43(5.7,1.25) 44(5.7,1.75) 45(5.7,2.25) 46(5.7,2.75) 47(5.7,3.25) 48(5.7,3.75)
  rrect33% 0.3x1.5 smd paste+0 mask+0: 17(-3.75,-5.7) 18(-3.25,-5.7) 19(-2.75,-5.7) 20(-2.25,-5.7) 21(-1.75,-5.7) 22(-1.25,-5.7) 23(-0.75,-5.7) 24(-0.25,-5.7) 25(0.25,-5.7) 26(0.75,-5.7) 27(1.25,-5.7) 28(1.75,-5.7) 29(2.25,-5.7) 30(2.75,-5.7) 31(3.25,-5.7) 32(3.75,-5.7) 49(3.75,5.7) 50(3.25,5.7) 51(2.75,5.7) 52(2.25,5.7) 53(1.75,5.7) 54(1.25,5.7) 55(0.75,5.7) 56(0.25,5.7) 57(-0.25,5.7) 58(-0.75,5.7) 59(-1.25,5.7) 60(-1.75,5.7) 61(-2.25,5.7) 62(-2.75,5.7) 63(-3.25,5.7) 64(-3.75,5.7)
  silkscreen extent -7.12,-5.1 5.1,5.1, body extent -6.55,-6.55 6.55,6.55, height 0.25
PWP0020AC-MFG [mm] "Recommended Land Pattern"
  rrect22% 1.5x0.45 smd paste+0 mask+0: 1(-2.9,2.925) 2(-2.9,2.275) 3(-2.9,1.625) 4(-2.9,0.975) 5(-2.9,0.325) 6(-2.9,-0.325) 7(-2.9,-0.975) 8(-2.9,-1.625) 9(-2.9,-2.275) 10(-2.9,-2.925) 11(2.9,-2.925) 12(2.9,-2.275) 13(2.9,-1.625) 14(2.9,-0.975) 15(2.9,-0.325) 16(2.9,0.325) 17(2.9,0.975) 18(2.9,1.625) 19(2.9,2.275) 20(2.9,2.925)
  rrect3% 3.4x6.5 smd paste-1000 mask-1000: 21(0,0)
  silkscreen extent -3.52,-3.62 2.25,3.82, body extent -3.2,-3.25 3.2,3.25, height 1.2
SMB-Bi [mm] "Molded Diode, 2-Leads, Body 5.4x3.6mm, IPC Medium Density, based on OnSemi component dimensions"
  rect 2.159x2.743 smd: 1(-2.21,0) 2(2.21,0)
  silkscreen extent -3.17,-1.99 3.17,1.99, body extent -2.65,-1.85 2.65,1.85, height 2.26
SMC_Bi [mil] "SMC, no polarity mark"
  rect 110x150 smd: 1(-140.49,0) 2(140.49,0)
  body extent -156,-116 156,116, height 92
TI_Stacked_Overlay_Small [mm]
  silkscreen extent -10.63,-2.49 10.63,2.49
TP_SM_1MM [mm] "1mm Test Point, SMT"
  round 1 smd paste-0.5: 1(0,0)
WCAP-ATUL_D10H12.5 [mm] "Aluminum Electrolytic Capacitors, 10x12.5mm"
  rrect50% 1.4x1.4 hole 0.9: 1(2.5,0)
  round 1.4 hole 0.9: 2(-2.5,0)
  silkscreen extent -5.25,-5.25 5.25,5.25, body extent -4.99,-5 5,5, height 12.81
WCAP-ATUL_D10H20 [mm] "Aluminum Electrolytic Capacitors, 10x20mm"
  rrect50% 1.4x1.4 hole 0.9: 1(2.5,0)
  round 1.4 hole 0.9: 2(-2.5,0)
  silkscreen extent -5.25,-5.25 5.25,5.25, body extent -4.99,-5 4.99,5, height 20.31
WCAP-CSGP_0603_L1.6W0.8H0.8_Reflow [mm] "Ceramic Capacitors, body 1.6x0.8mm"
  rect 0.8x0.8 smd: 1(-0.75,0) 2(0.75,0)
  body extent -0.8,-0.4 0.8,0.4, height 0.8
WCAP-CSGP_0805_L2W1.25H0.8_Reflow [mm] "Ceramic Capacitors, body 2x1.25mm"
  rect 0.9x1.3 smd: 1(-0.95,0) 2(0.95,0)
  body extent -1,-0.62 1,0.63, height 0.8
WCAP-CSST_1210_L3.2W2.5H2.5 [mm] "Soft Termination MLCC, body 3.20x2.50mm"
  rect 0.9x2.5 smd: 1(-1.55,0) 2(1.55,0)
  silkscreen extent -0.8,-1.5 0.8,1.5, body extent -1.6,-1.25 1.6,1.25, height 2.5
WE-HCC_1210 [mm] "WURTH"
  rect 2.9x5.4 smd: 1(-4.95,0) 2(4.95,0)
  silkscreen extent -6,-5.9 6,5.9, body extent -6,-5.85 6,5.85, height 10
WEEE_Minimum [mm] "WEEElie bin"
  silkscreen extent -2.42,-4.38 2.52,2.65
WL-SMCW_0603_150060xx75000 [mm] "SMD Mono-color Chip LED, body 1.60 x 0.80 mm"
  rect 0.8x0.8 smd: 1(-0.8,0) 2(0.8,0)
  silkscreen extent -1.55,-0.4 -1.4,0.4, body extent -0.8,-0.4 0.8,0.4, height 0.7
WL-SMCW_GREEN [mm] "WURTH"
  rect 0.8x0.8 smd: 1(-0.8,0) 2(0.8,0)
  silkscreen extent -1.9,-0.8 1.2,0.8, body extent -0.85,-0.45 0.85,0.45, height 0.8
WL-SMCW_RED [mm] "WURTH"
  rect 0.8x0.8 smd: 1(-0.8,0) 2(0.8,0)
  silkscreen extent -1.9,-0.8 1.2,0.8, body extent -0.85,-0.45 0.85,0.45, height 0.8
Wurth_60900213421 [mil] "Shunt, 2.54mm, Black"
  round 1 on Mech3: 0(0,0)
  body extent -98,-48 98,48, height 338
WURTH_61300211121 [mm] "Header, 2.54mm, 2x1, TH"
  rrect50% 1.65x1.65 hole 1.15: 1(-1.27,0)
  round 1.65 hole 1.15: 2(1.27,0)
  body extent -2.54,-1.27 2.54,1.27, height 8.54
WURTH_61300411121 [mm] "Header, 2.54mm, 4x1, TH"
  rrect50% 1.65x1.65 hole 1.15: 1(-3.81,0)
  round 1.65 hole 1.15: 2(-1.27,0) 3(1.27,0) 4(3.81,0)
  body extent -5.08,-1.27 5.08,1.27, height 8.54
WURTH_61301021121 [mm] "Header, 2.54mm, 5x2, TH"
  rrect25% 1.65x1.65 hole 1.15: 1(-5.08,-1.27)
  round 1.65 hole 1.15: 2(-5.08,1.27) 3(-2.54,-1.27) 4(-2.54,1.27) 5(0,-1.27) 6(0,1.27) 7(2.54,-1.27) 8(2.54,1.27) 9(5.08,-1.27) 10(5.08,1.27)
  silkscreen extent -6.35,-2.9 6.35,2.54, body extent -6.35,-2.54 6.35,2.54, height 8.54

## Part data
C1: library part CMP-0120896-1, "1 µF ±10% 50V Ceramic Capacitor X7R 0603 (1608 Metric)", Digikey Part Number=732-885012206126CT-ND, Manufacturer="Wurth Electronics", Mouser Part Number=710-885012206126, Operating Temperature Range="-55°C to +125°C", TempCo=15%, Temperature Characteristic=X7R, Tolerance_%=10%, ValueDisplayed=1uF
C2: library part CMP-0120893-1, "10000 pF ±10% 25V Ceramic Capacitor X7R 0603 (1608 Metric)", Digikey Part Number=732-7983-1-ND, Manufacturer="Wurth Electronics", Mouser Part Number=710-885012206065, Operating Temperature Range="-55°C to +125°C", TempCo=15%, Temperature Characteristic=X7R, Tolerance_%=10%, ValueDisplayed=10nF
C3: library part CMP-0119380-1, "WCAP-CSGP Multilayer Ceramic Chip Capacitor, General Purpose, size 0603, X7R Class II, 470nF, 25VDC", Capacitance Tolerance=+/-10%, Case/Size Code=0603, Insulation Resistance=1.1GOhm, Manufacturer="Wurth Elektronik", Operating Temperature Max=125°C, Operating Temperature Min=-55°C, Rated Voltage (DC)=25V
C4: library part CMP-0006837-4, "CAP, CERM, 0.1 uF, 50 V, +/- 10%, X7R, 0603", Cap_Case=0603, Manufacturer="Wurth Elektronik", TempCo=X7R, Tolerance_%=10%, Value1=Unknown, Value2=50V, ValueDisplayed=0.1uF
C5: library part CMP-0860569-1, "CAP, CERM, 10 µF, 25 V,+/- 10%, X5R, 0603", Cap_Case=0603, Manufacturer=MuRata, TempCo=X5R, Tolerance_%=10%, Value2=25V, ValueDisplayed=10µF
C6 C7: library part CMP-0120892-1, "22 pF ±5% 50V Ceramic Capacitor C0G, NP0 0402 (1005 Metric)", Digikey Part Number=732-7471-1-ND, Manufacturer="Wurth Electronics", Mouser Part Number=710-885012005057, Operating Temperature Range="-55°C to +125°C", TempCo=30ppm/°C, Temperature Characteristic=NP0, Tolerance_%=5%, ValueDisplayed=22pF
C8 C12 C17 C20 C24 C25 C28: library part CMP-0006623-2, "CAP, CERM, 0.1 uF, 6.3 V, +/- 10%, X7R, 0402", Cap_Case=0402, Manufacturer=MuRata, Supplier Part Number 1=GRM155R70J104KA01D-ND, TempCo=X7R, Tolerance_%=10%, Value1=Unknown, Value2=6.3V, ValueDisplayed=0.1uF
C9 C10 C11 C15 C18: library part CMP-0006658-2, "CAP, CERM, 0.01 uF, 25 V, +/- 10%, X7R, 0402", Cap_Case=0402, Manufacturer=MuRata, Supplier Part Number 1=490-1312-1-ND, TempCo=X7R, Tolerance_%=10%, Value1=Unknown, Value2=25V, ValueDisplayed=0.01uF
C13: library part CMP-0006831-4, "CAP, CERM, 1 uF, 16 V, +/- 10%, X7R, 0603", Cap_Case=0603, Manufacturer="Wurth Elektronik", Supplier Part Number 1=710-885012206052, TempCo=X7R, Tolerance_%=10%, Value1=Unknown, Value2=16V, ValueDisplayed=1uF
C14: library part CMP-0078154-1, "CAP, CERM, 10 µF, 16 V,+/- 20%, X5R, 0805", Cap_Case=0805, Manufacturer="Wurth Elektronik", Supplier Part Number 1=732-7624-1-ND, TempCo=X5R, Tolerance_%=20%, Value2=16V, ValueDisplayed=10µF
C16 C23: library part CMP-0006415-2, "CAP, CERM, 12 pF, 50 V, +/- 5%, C0G/NP0, 0402", Cap_Case=0402, Manufacturer=MuRata, Supplier Part Number 1=14T3292, TempCo=C0G/NP0, Tolerance_%=5%, Value1=Unknown, Value2=50V, ValueDisplayed=12pF
C19 C26 C29: library part CMP-0006276-2, "CAP, CERM, 1 uF, 25 V, +/- 10%, X5R, 0402", Cap_Case=0402, Manufacturer=TDK, Supplier Part Number 1=445-9066-1-ND, TempCo=X5R, Tolerance_%=10%, Value1=Unknown, Value2=25V, ValueDisplayed=1uF
C21: library part CMP-0750039-1, "CAP, CERM, 0.01 µF, 50 V,+/- 10%, X7R, 0603", Cap_Case=0603, Manufacturer="Wurth Elektronik", TempCo=X7R, Tolerance_%=10%, Value2=50V, ValueDisplayed=0.01µF
C22: library part CMP-0049204-1, "0.1 µF ±10% 50V Ceramic Capacitor X7R 0603 (1608 Metric)", Digikey Part Number=732-8013-1-ND, Manufacturer=Wurth, Mouser Part Number=710-885012206095, Operating Temperature Range="-55°C to +125°C", TempCo=15%, Temperature Characteristic=X7R, Tolerance_%=10%, ValueDisplayed=100nF
C27: library part CMP-0006906-5, "CAP, CERM, 2.2 uF, 10 V, +/- 10%, X5R, 0603", Cap_Case=0603, Manufacturer=Kemet, Supplier Part Number 1=399-4911-1-ND, TempCo=X5R, Tolerance_%=10%, Value1=Unknown, Value2=10V, ValueDisplayed=2.2uF
C30: library part CMP-0119330-1, "WCAP-CSGP Multilayer Ceramic Chip Capacitor, General Purpose, size 0603, X7R, 2.2µF, 10VDC", Capacitance Tolerance=+/-10%, Case/Size Code=0603, Insulation Resistance=0.02GOhm, Manufacturer="Wurth Elektronik", Operating Temperature Max=125°C, Operating Temperature Min=-55°C, Rated Voltage (DC)=10V
C31: library part CMP-0119538-1, "WCAP-CSGP Multilayer Ceramic Chip Capacitor, General Purpose, size 0805, X7R, 22nF, 100VDC", Capacitance Tolerance=+/-10%, Case/Size Code=0805, Insulation Resistance=4.5GOhm, Manufacturer="Wurth Elektronik", Operating Temperature Max=125°C, Operating Temperature Min=-55°C, Rated Voltage (DC)=100V
C32: library part CMP-0119921-1, "WCAP-CSST Multilayer Ceramic Chip Capacitor, Soft Termination, size 1210, X7R Class II, 2.2µF, 100VDC", Capacitance Tolerance=+/-10%, Case/Size Code=1210, Insulation Resistance=0.05GOhm, Manufacturer="Wurth Elektronik", Operating Temperature Max=125°C, Operating Temperature Min=-55°C, Rated Voltage (DC)=100V
C33: library part CMP-0007891-2, "CAP, CERM, 1 uF, 100 V, +/- 10%, X7S, 0805", Cap_Case=0805, Manufacturer=TDK, Supplier Part Number 1=445-5205-1-ND, TempCo=X7S, Tolerance_%=10%, Value1="0.008255 ohm", Value2=100V, ValueDisplayed=1uF
C39: library part CMP-0102580-1, "WCAP-ATUL Aluminum Electrolytic Capacitor, Radial, THT, D10 x H12.5mm, 47µF, 100V", Capacitance Tolerance=20%, Leakage Current=47uA, Manufacturer="Wurth Elektronik", Operating Temperature Max=105°C, Operating Temperature Min=-40°C, Rated Voltage (DC)=100V, Ripple Current=400mA
C40 C41 C46: library part CMP-0097312-1, "1 µF ±10% 100V Ceramic Capacitor X7R 1210 (3225 Metric)", Manufacturer="Wurth Electronics", Operating Temperature Range="-55°C to +125°C", TempCo=15%, Temperature Characteristic=X7R, Tolerance_%=10%, ValueDisplayed=1uF
C42 C48: library part CMP-0079993-1, "CAP, CERM, 0.01 µF, 100 V,+/- 10%, X7R, 0603", Cap_Case=0603, Manufacturer="Wurth Elektronik", Supplier Part Number 1=45AC8565, TempCo=X7R, Tolerance_%=10%, Value2=100V, ValueDisplayed=0.01µF
C43: library part CMP-0102582-1, "WCAP-ATUL Aluminum Electrolytic Capacitor, Radial, THT, D10 x H20mm, 82µF, 100V", Capacitance Tolerance=20%, Leakage Current=82uA, Manufacturer="Wurth Elektronik", Operating Temperature Max=105°C, Operating Temperature Min=-40°C, Rated Voltage (DC)=100V, Ripple Current=600mA
C44 C49: library part CMP-0097294-1, "0.1 µF ±10% 100V Ceramic Capacitor X7R 0603 (1608 Metric)", Digikey Part Number=732-885012206120TR-ND, Manufacturer="Wurth Electronics", Mouser Part Number=710-885012206120, Operating Temperature Range="-55°C to +125°C", TempCo=15%, Temperature Characteristic=X7R, Tolerance_%=10%, ValueDisplayed=100nF
C45: library part CMP-0006724-5, "CAP, CERM, 1000 pF, 100 V, +/- 10%, X7R, 0603", Cap_Case=0603, Manufacturer=AVX, Supplier Part Number 1=478-1199-1-ND, TempCo=X7R, Tolerance_%=10%, Value1="0.276 ohm", Value2=100V, ValueDisplayed=1000pF
C50: library part CMP-0119409-1, "WCAP-CSGP Multilayer Ceramic Chip Capacitor, General Purpose, size 0603, X7R, 1nF, 100VDC", Capacitance Tolerance=+/-10%, Insulation Resistance=10GOhm, Manufacturer="Wurth Elektronik", Operating Temperature Max=125°C, Operating Temperature Min=-55°C, Rated Voltage (DC)=100V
